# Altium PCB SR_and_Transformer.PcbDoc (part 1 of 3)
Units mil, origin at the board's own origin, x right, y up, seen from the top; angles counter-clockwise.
Board outline 2362.61 x 1852.83 mil, 12 copper layers (Top Layer, Layer 1, Layer 2, Layer 3, Layer 4, Layer 5, Layer 6, Layer 7, Layer 8, Layer 9, Layer 10, Bottom Layer), stack 88.072 mil thick; 104 components, 44 nets, 388 pads, 1030 vias.
Unrouted connection lines stored in the file: 6.
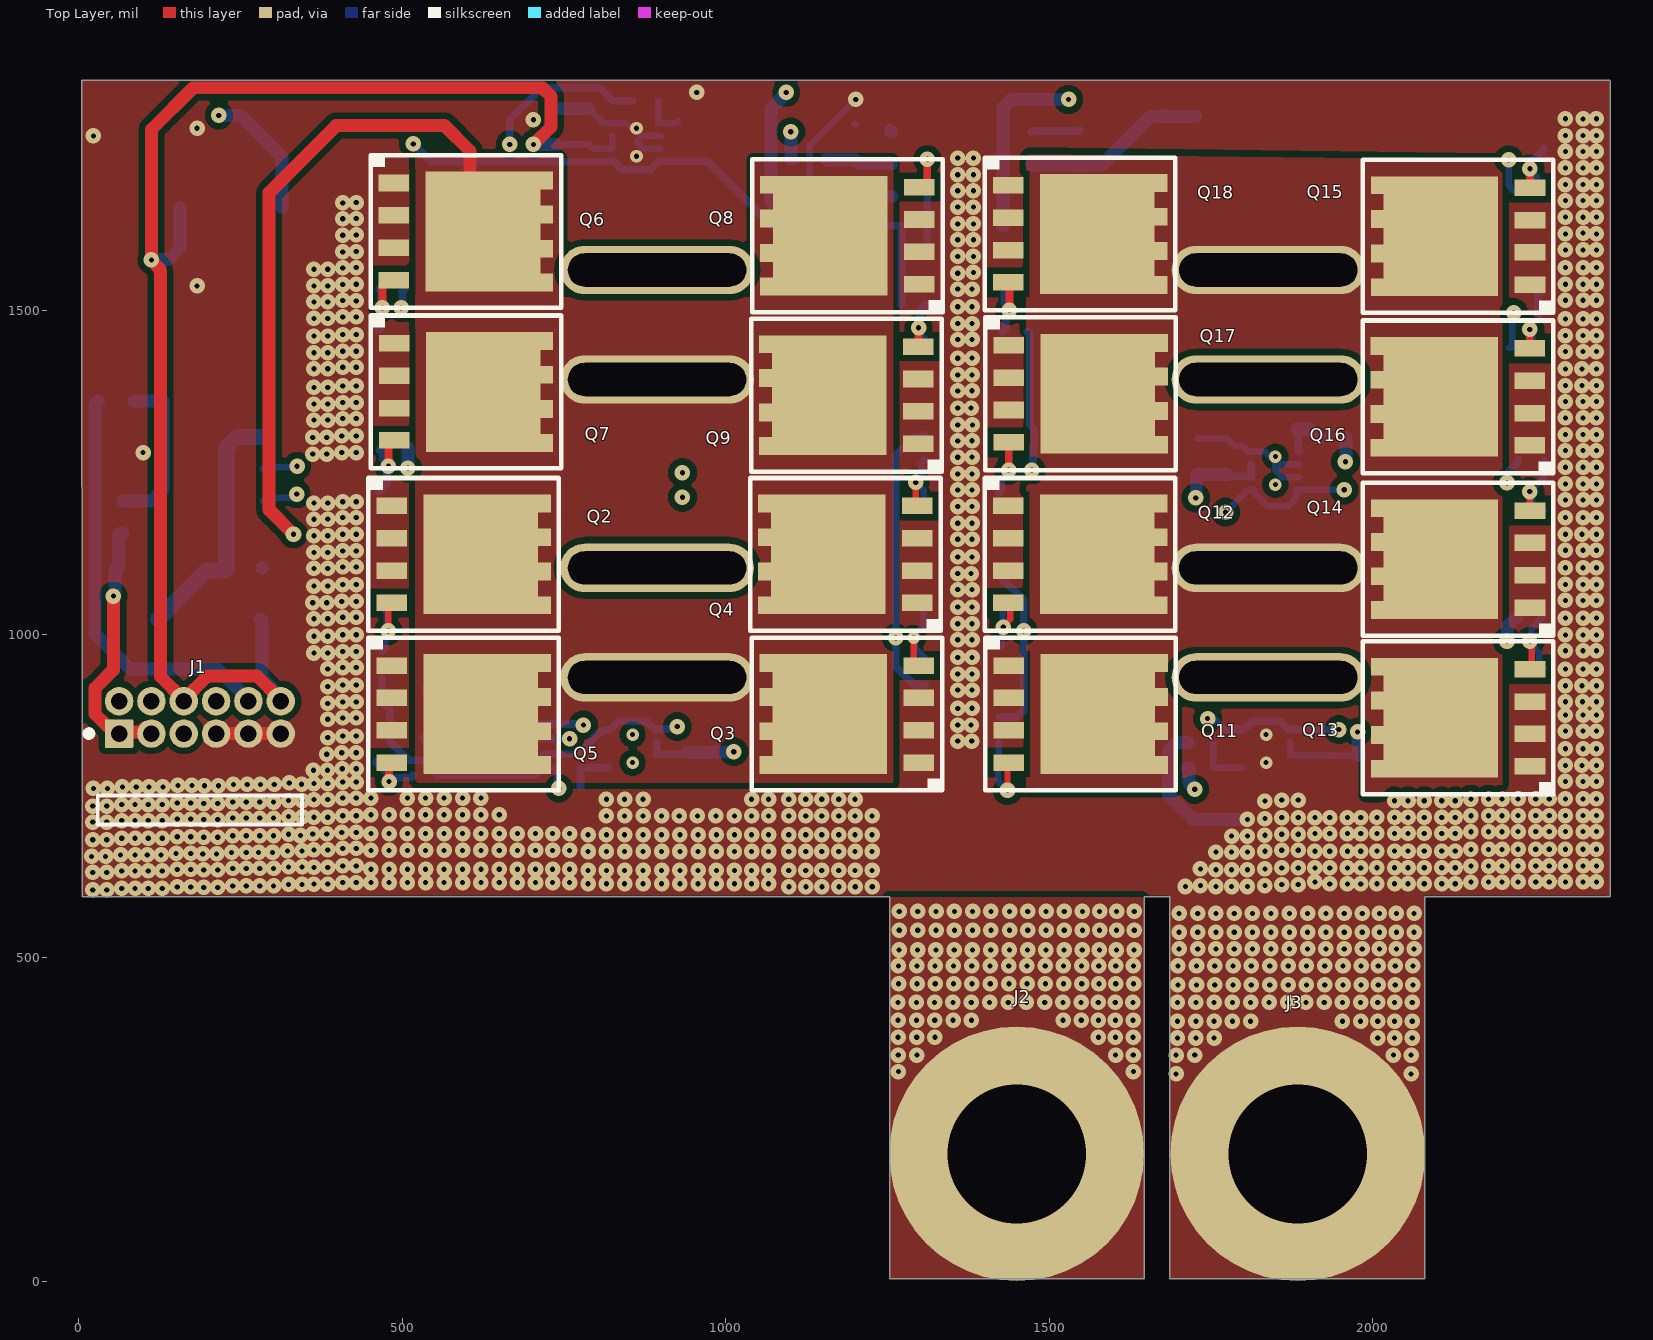
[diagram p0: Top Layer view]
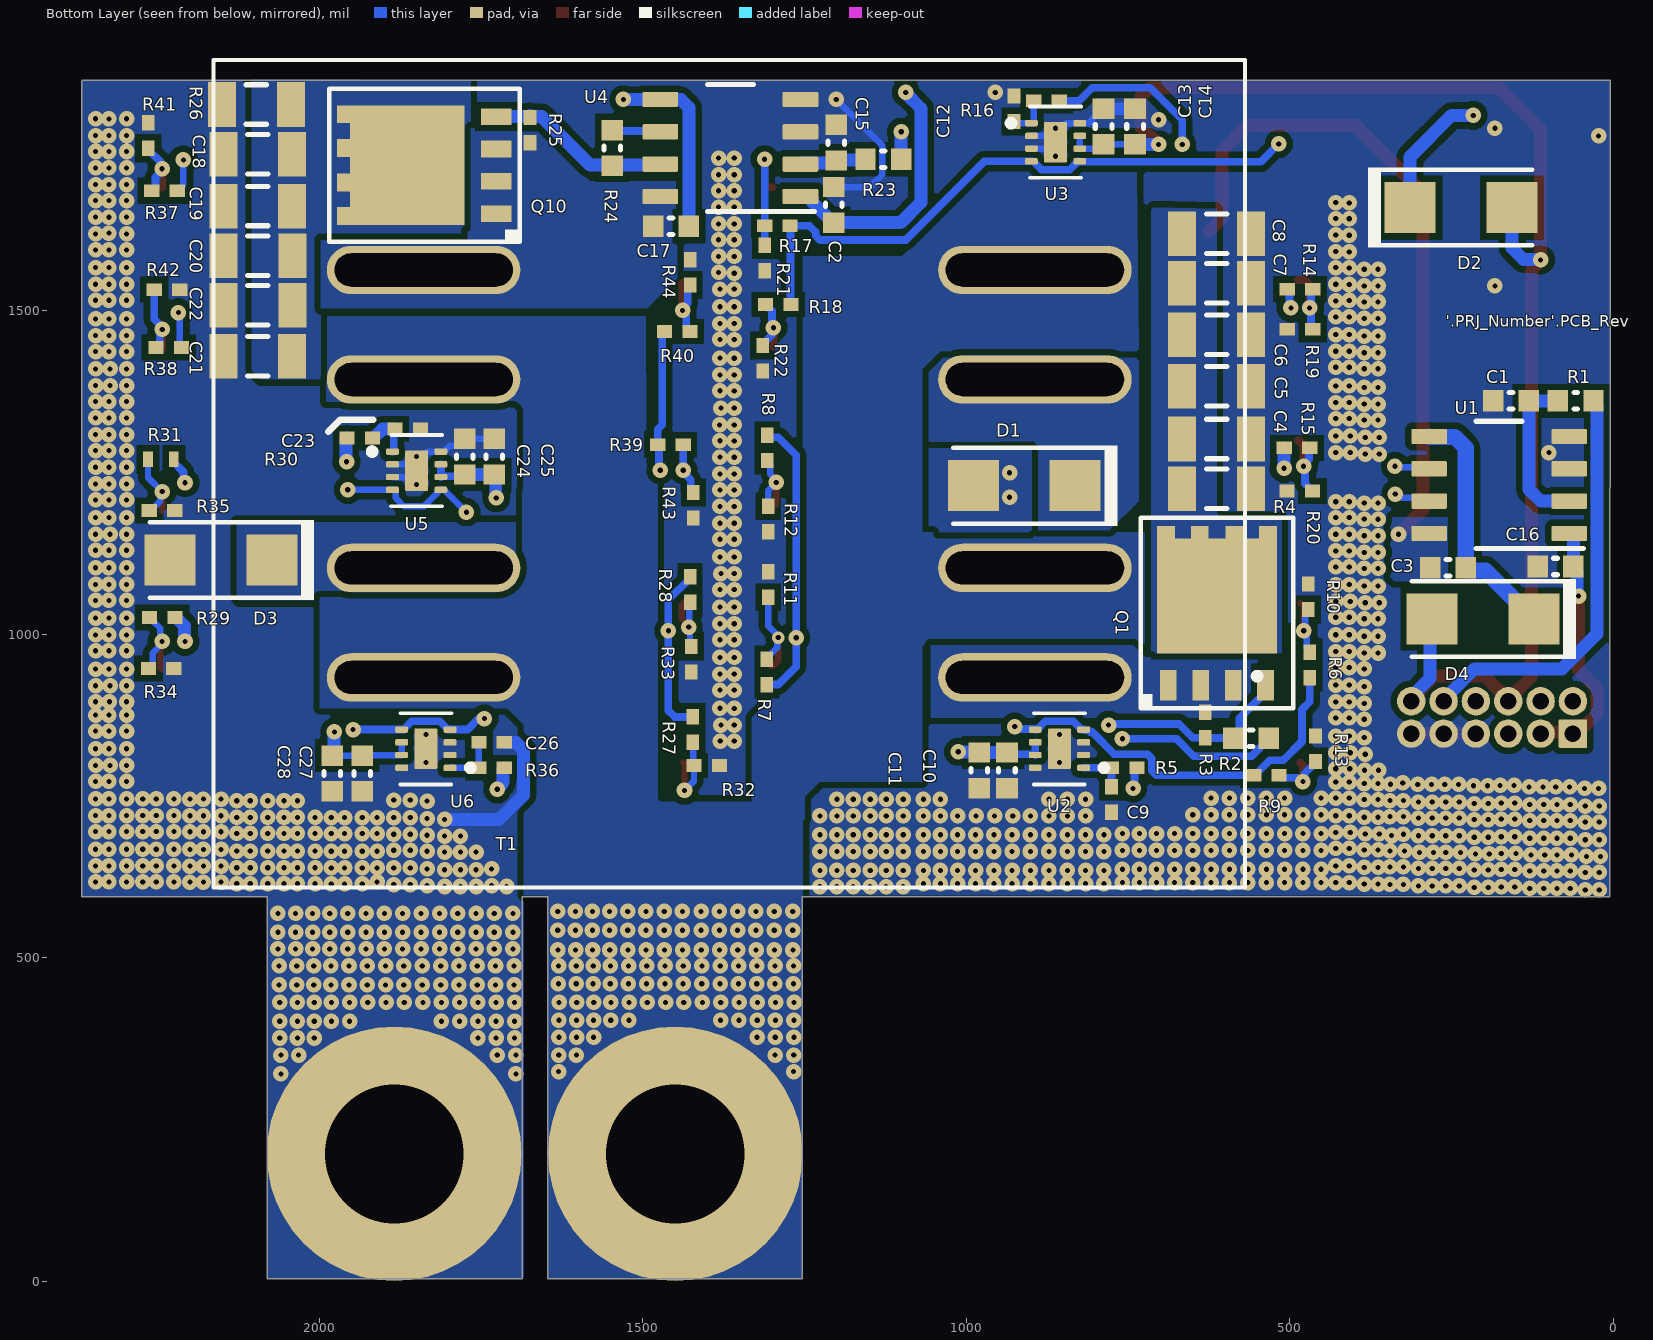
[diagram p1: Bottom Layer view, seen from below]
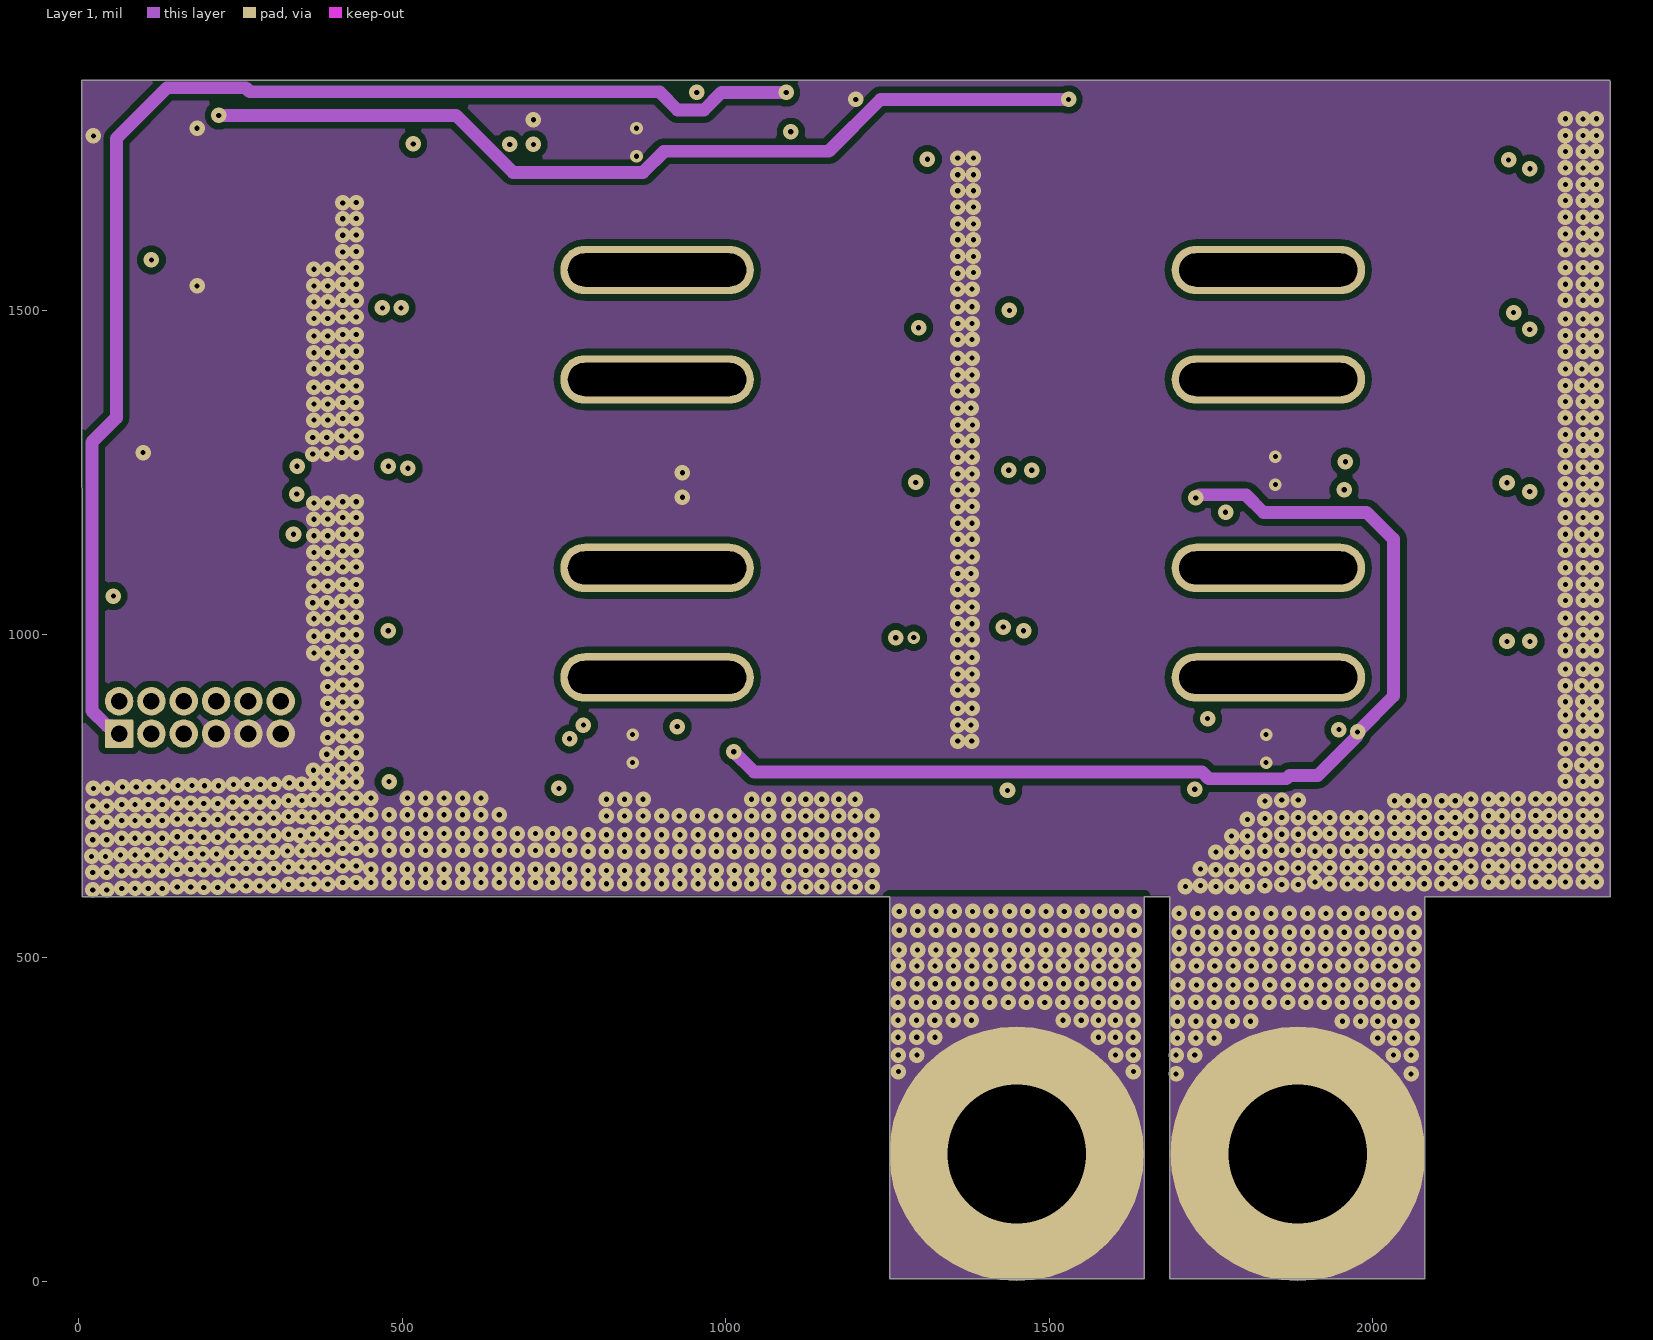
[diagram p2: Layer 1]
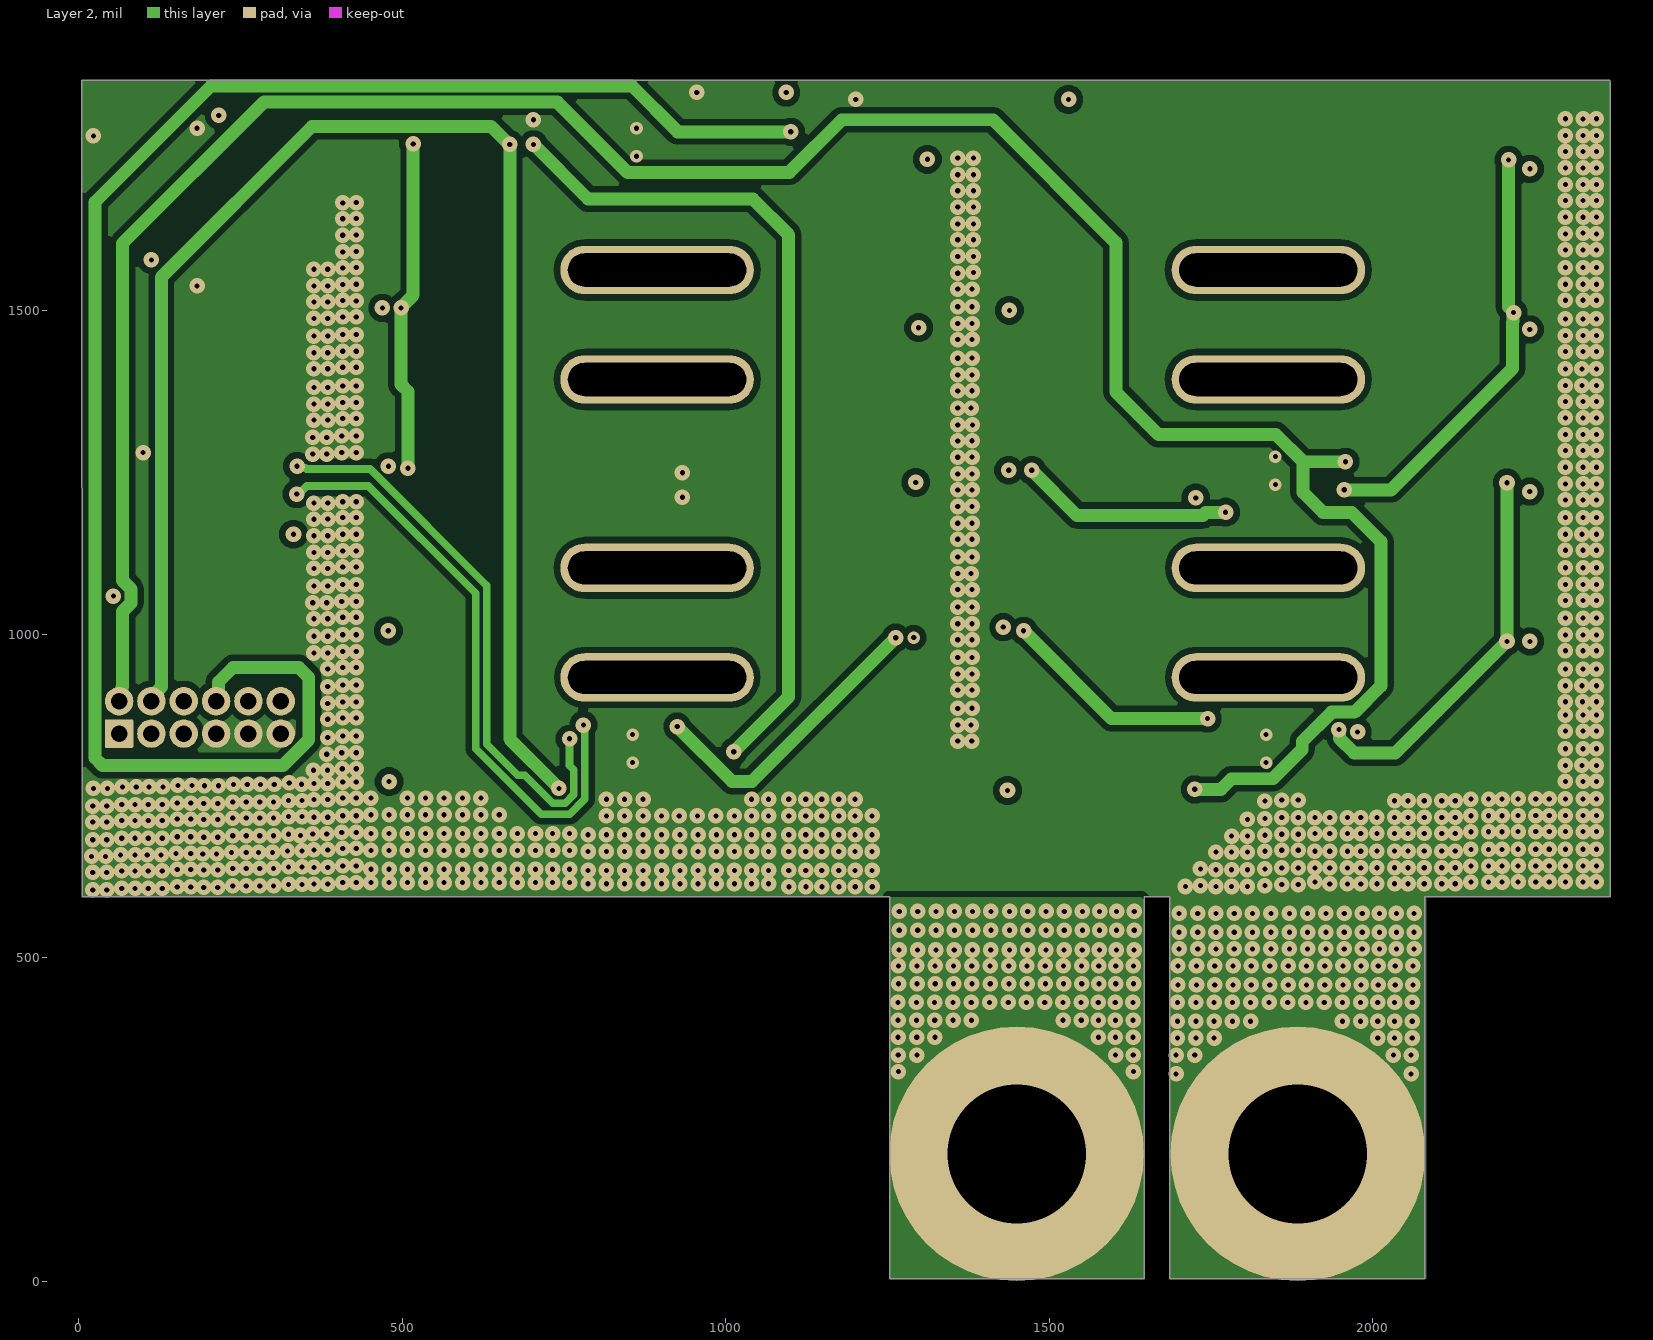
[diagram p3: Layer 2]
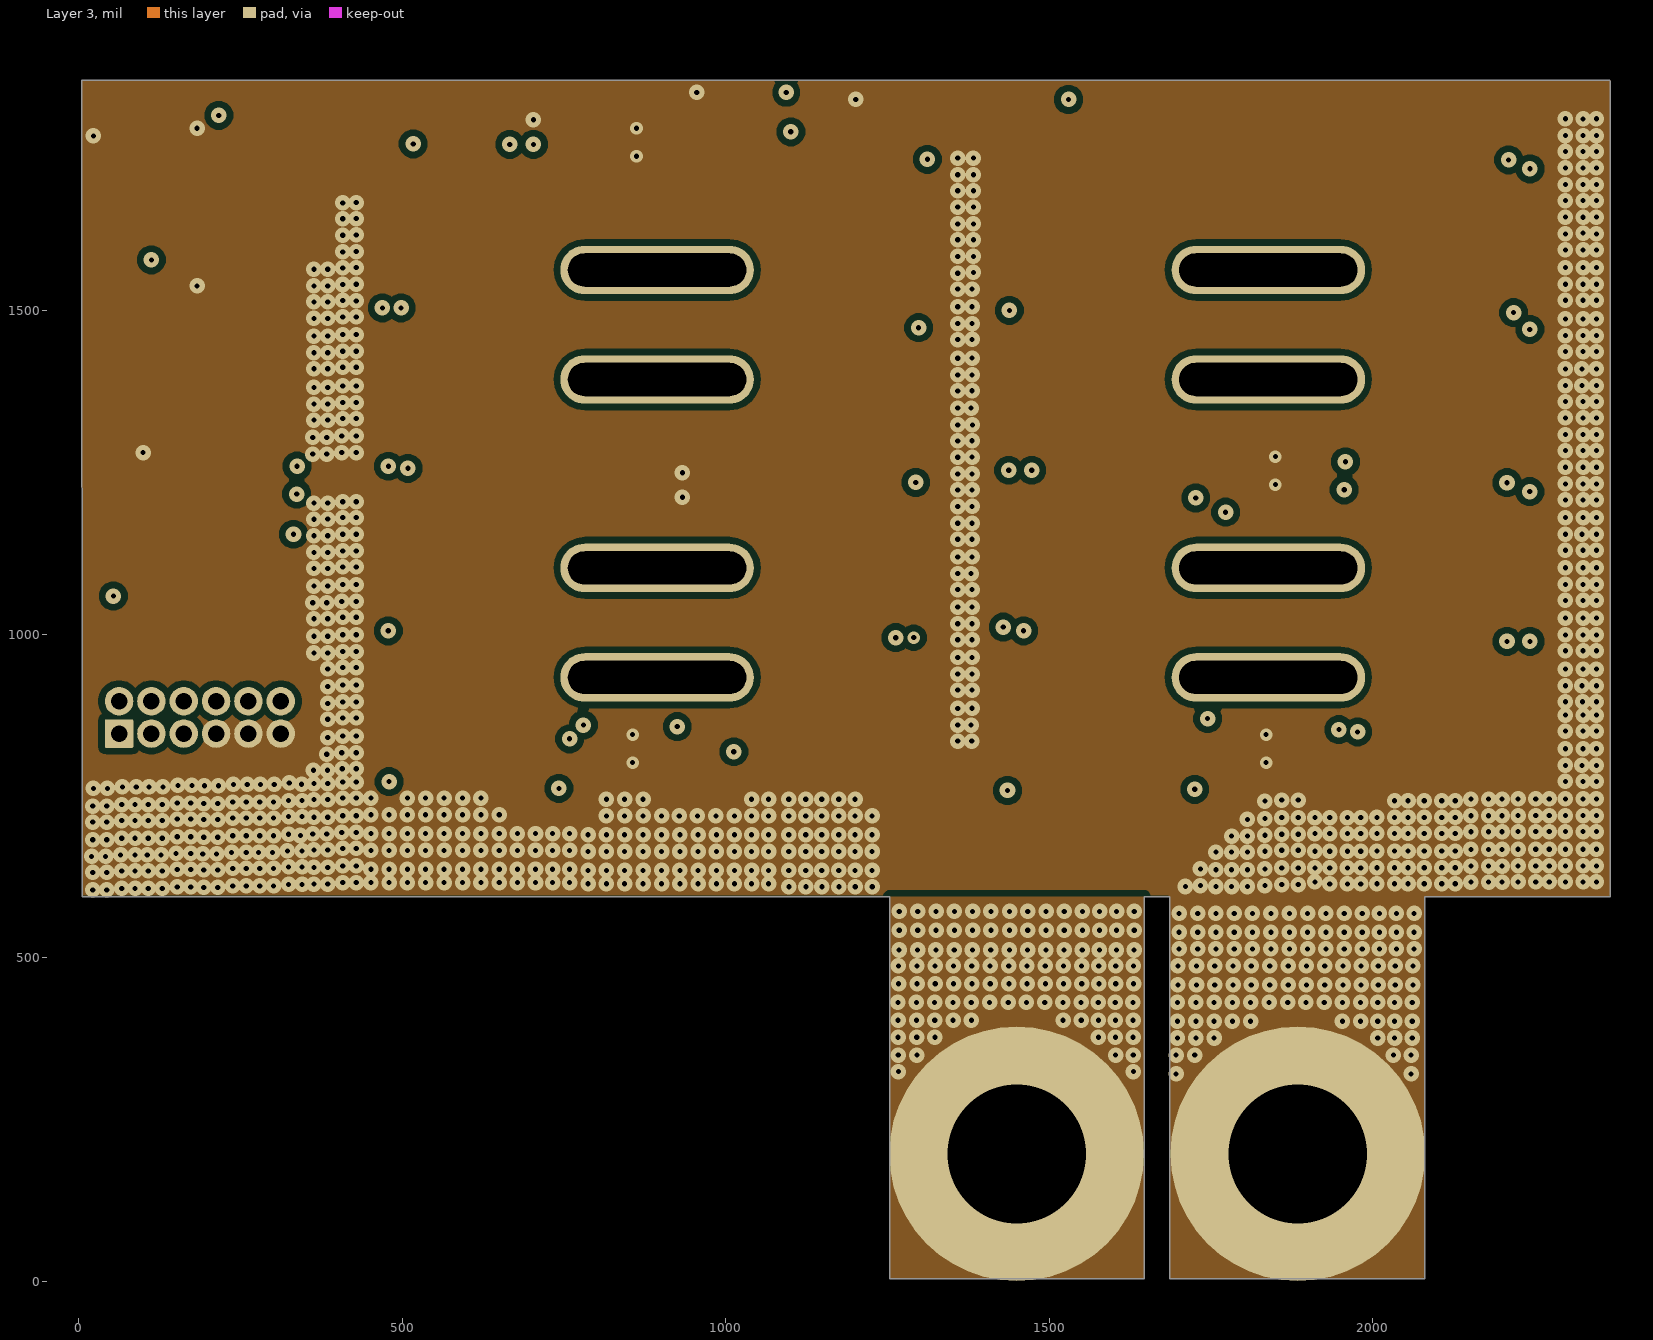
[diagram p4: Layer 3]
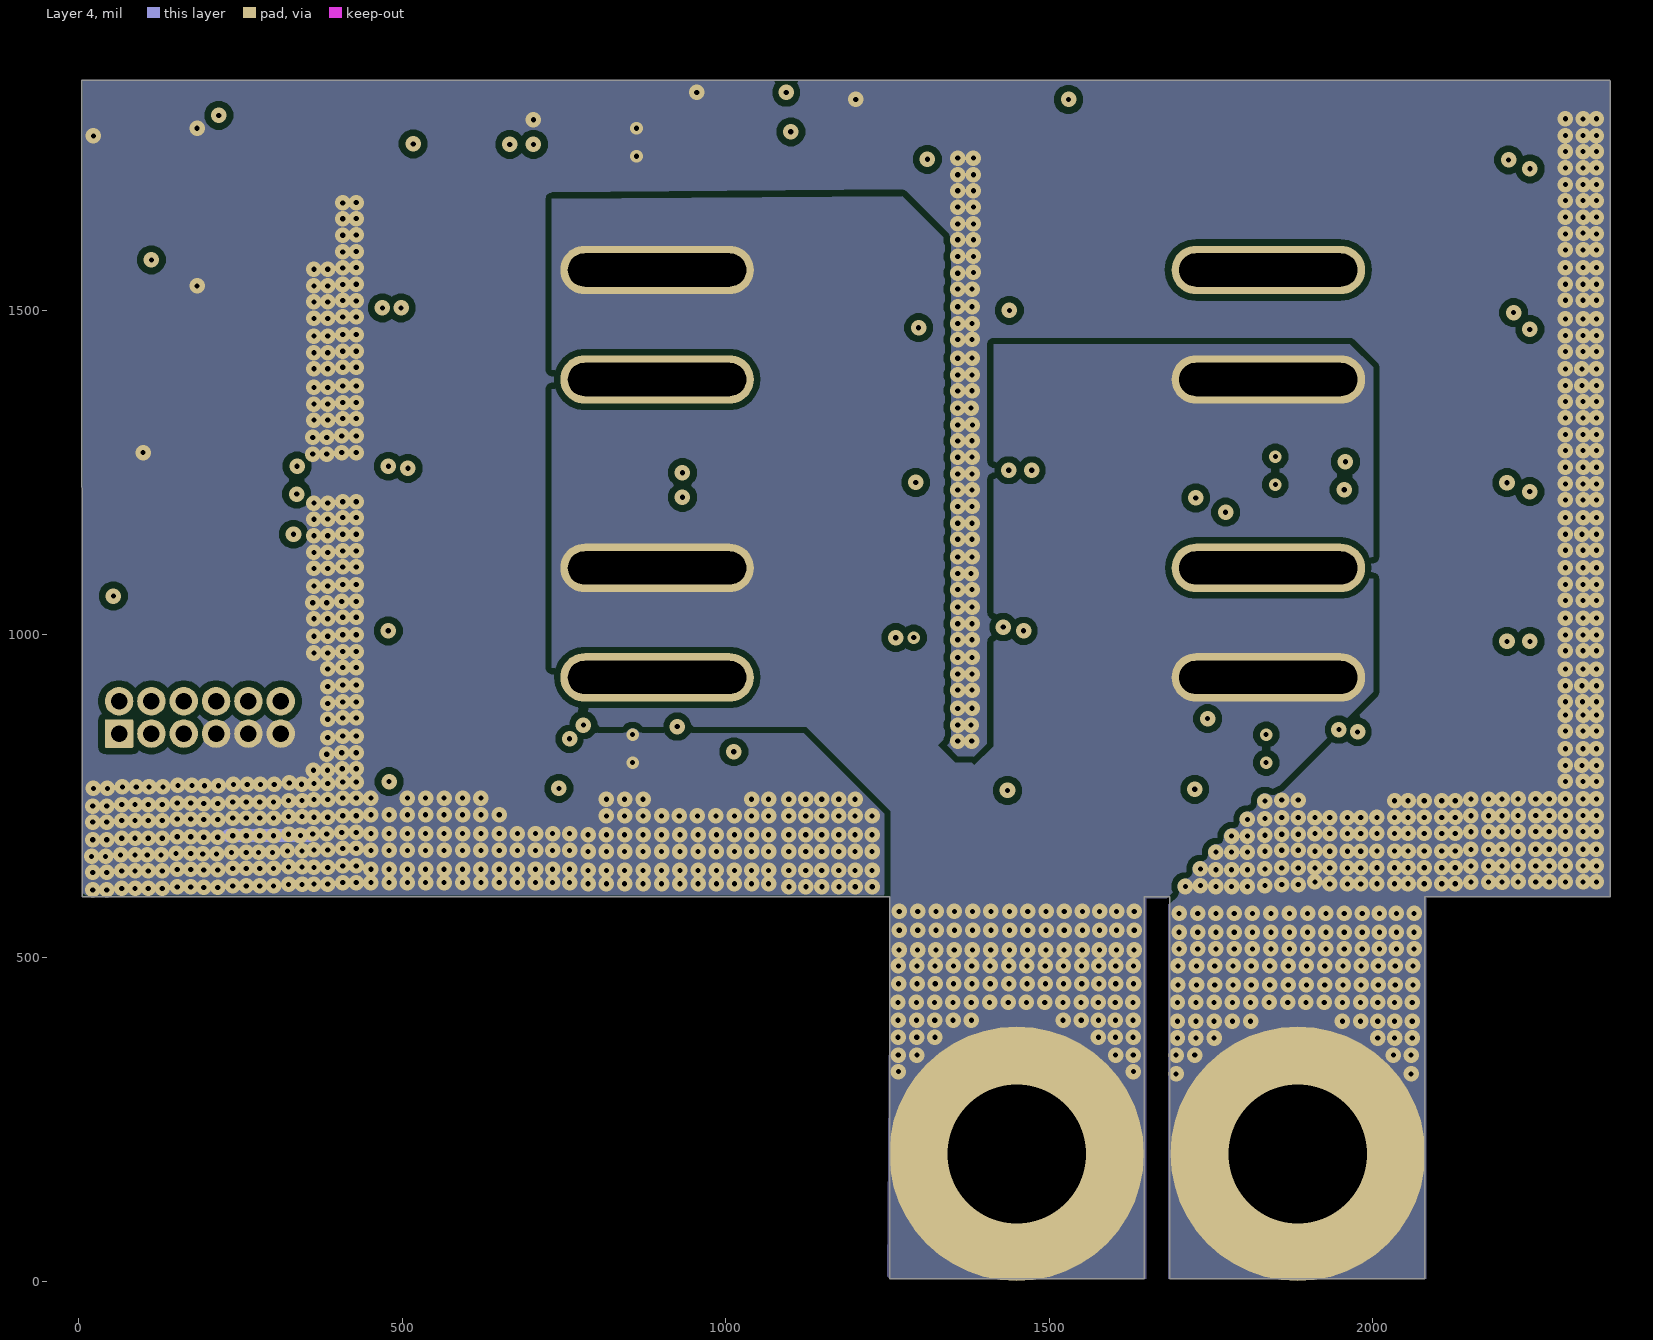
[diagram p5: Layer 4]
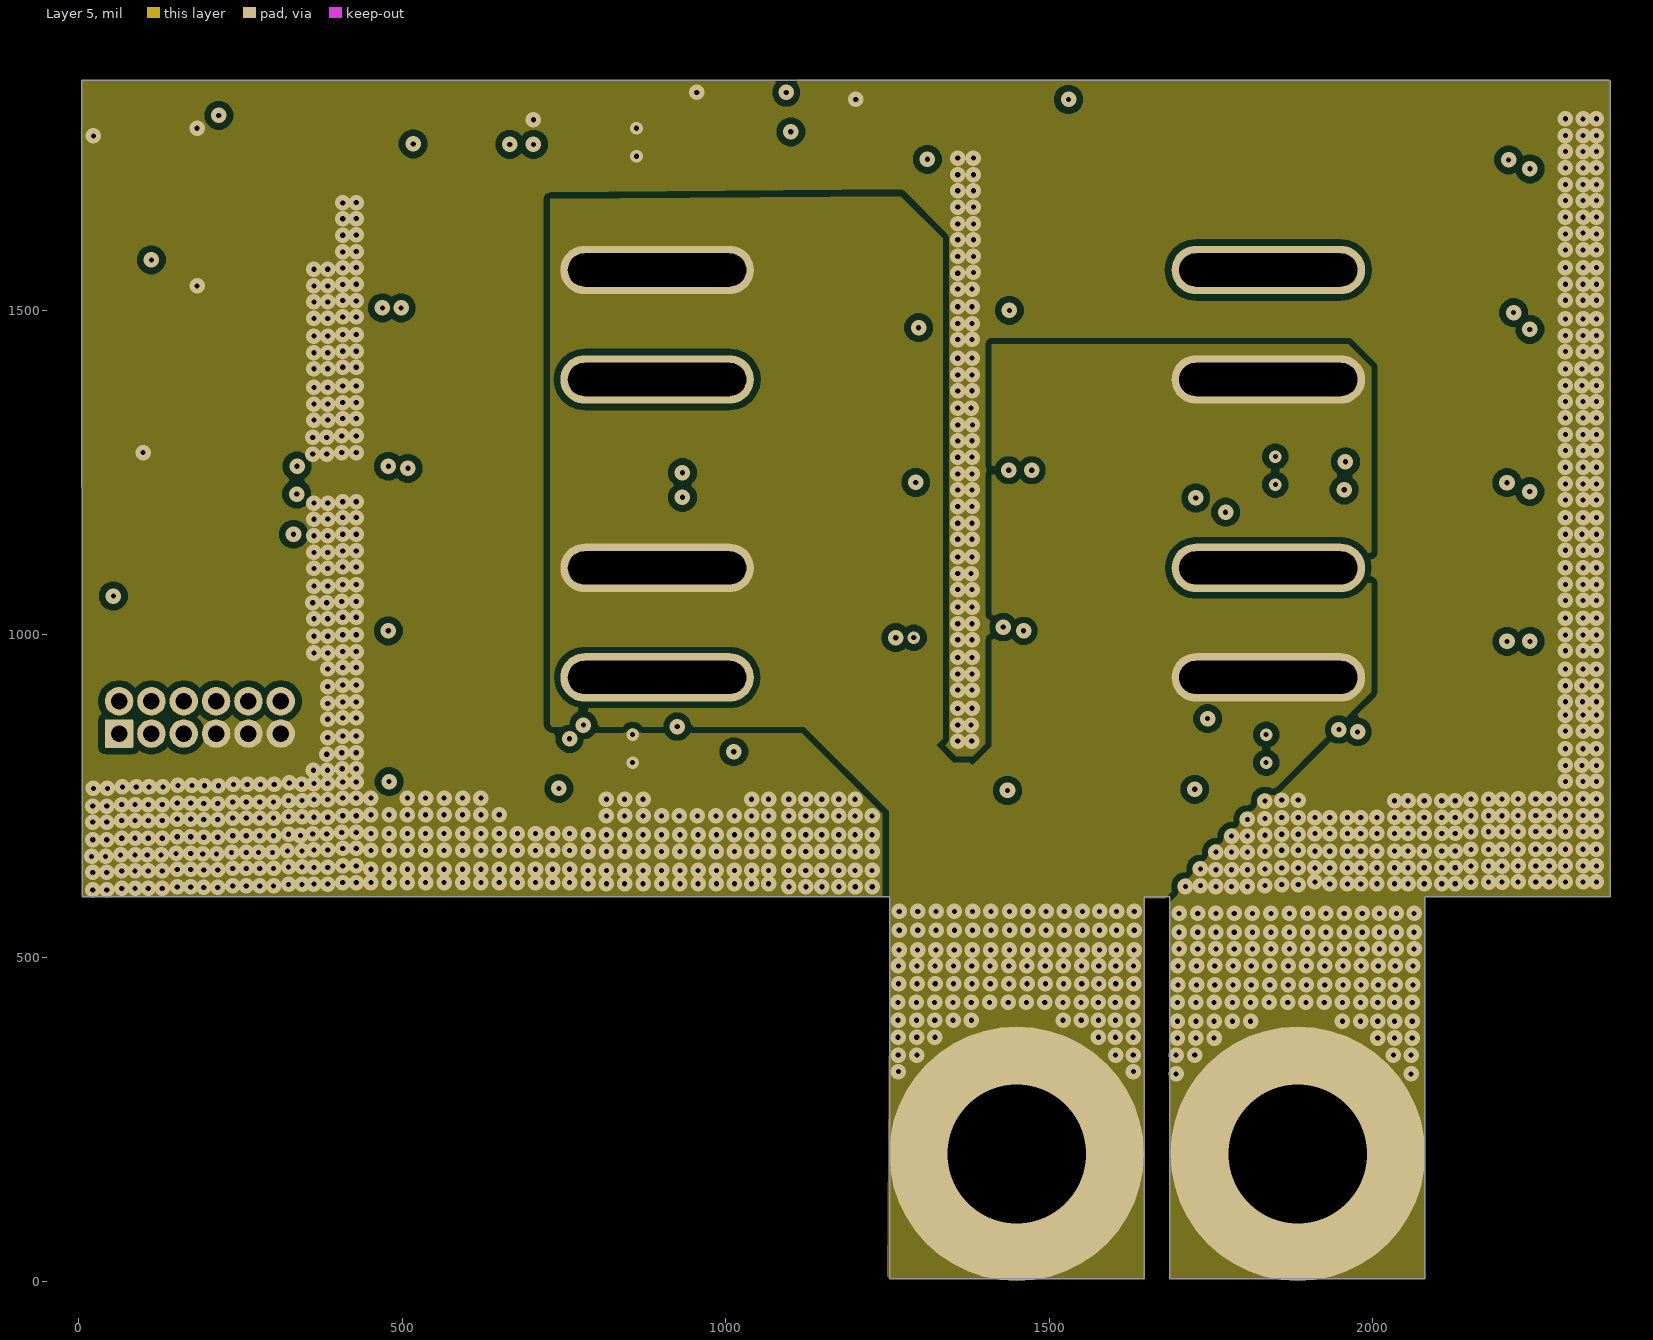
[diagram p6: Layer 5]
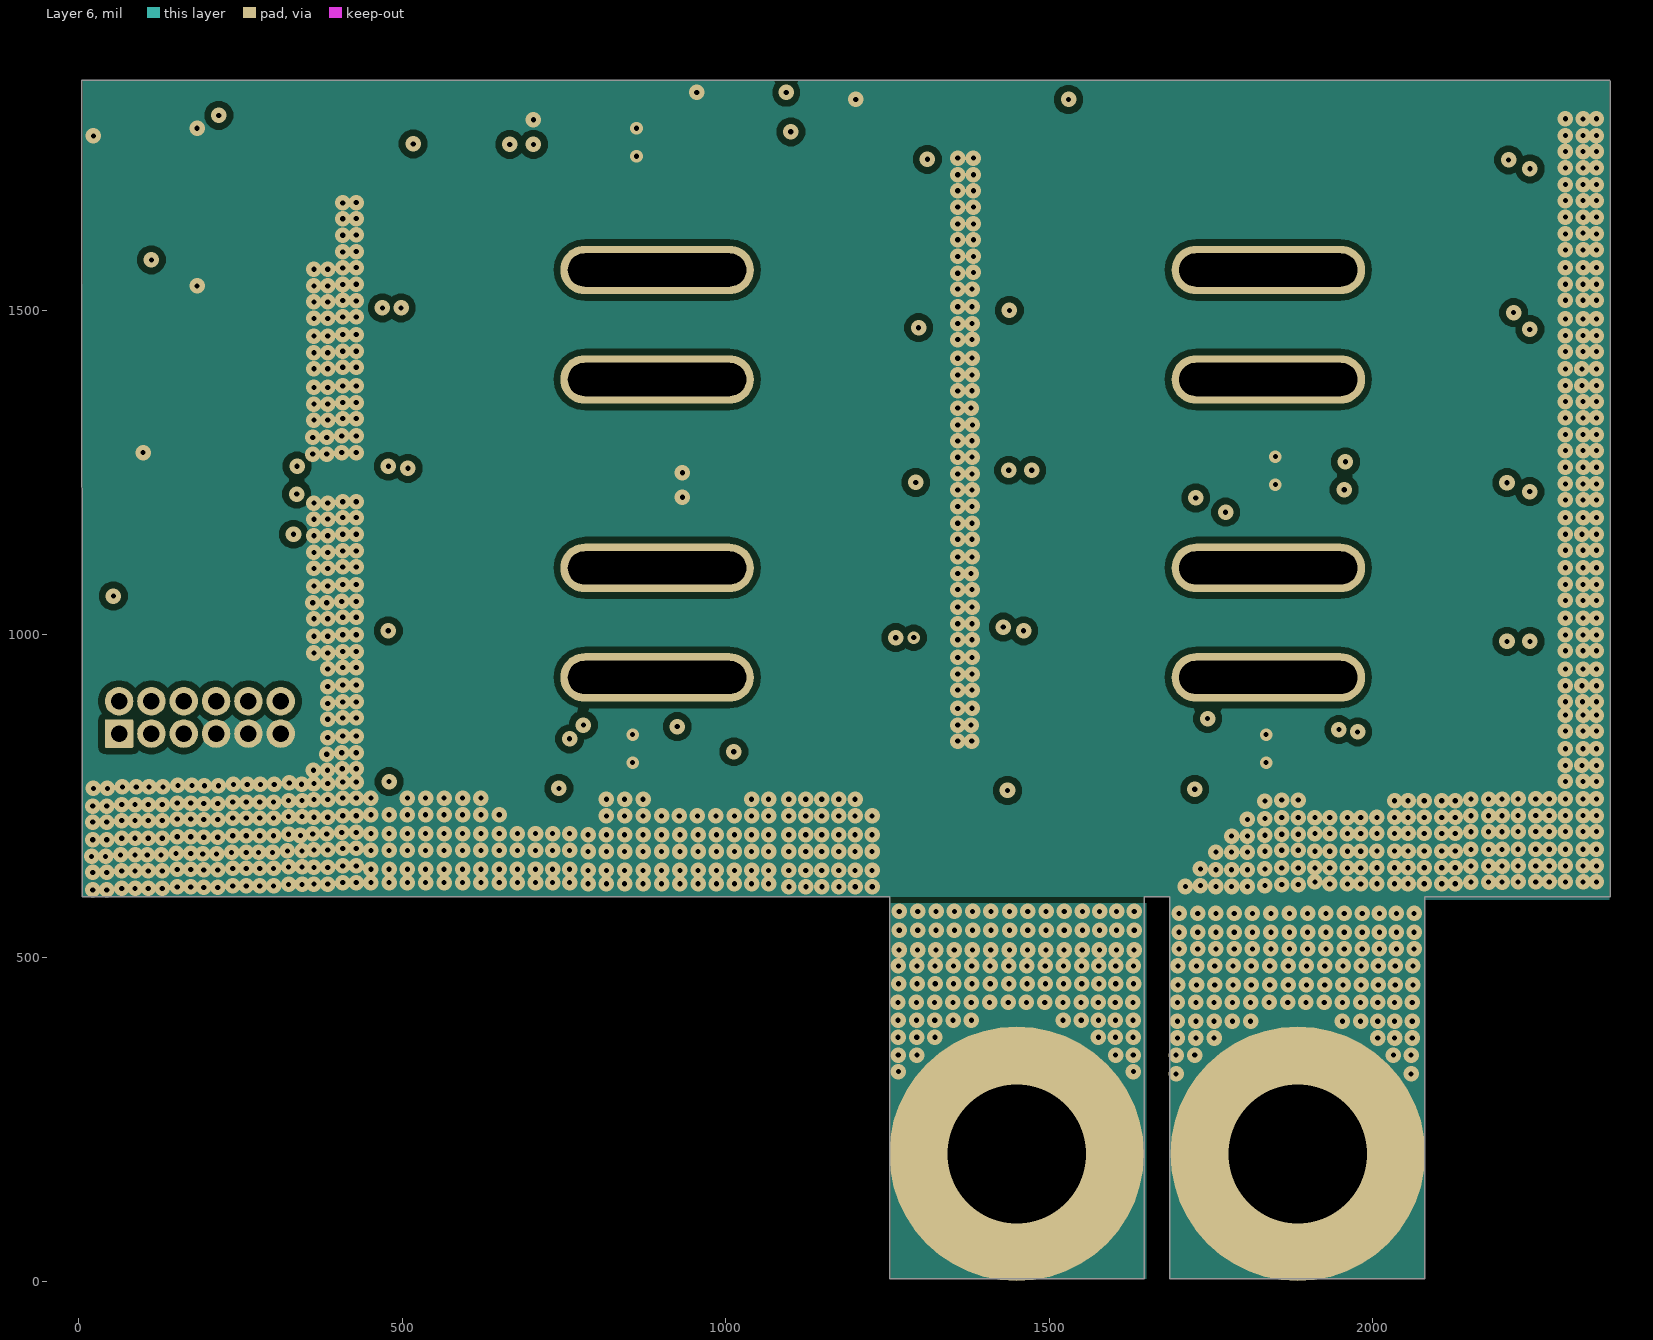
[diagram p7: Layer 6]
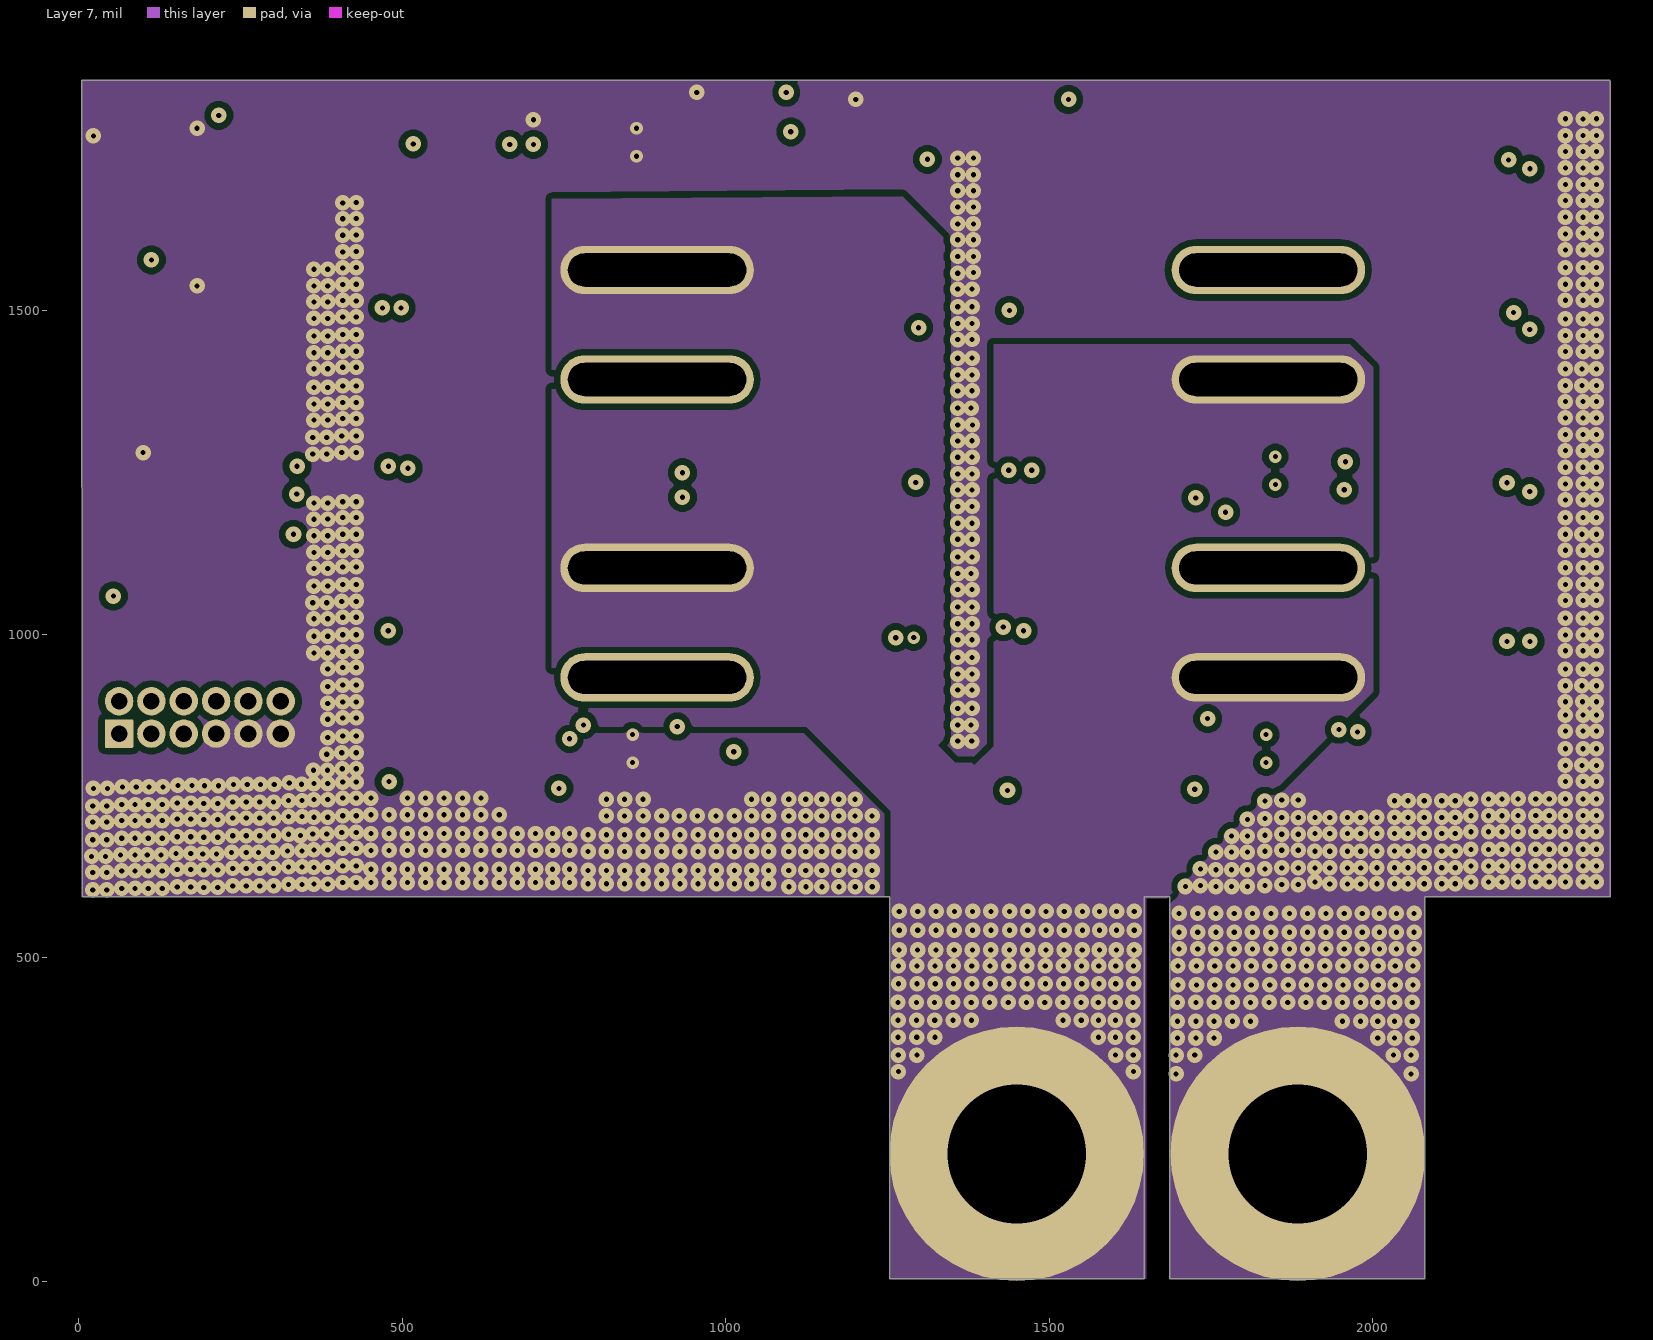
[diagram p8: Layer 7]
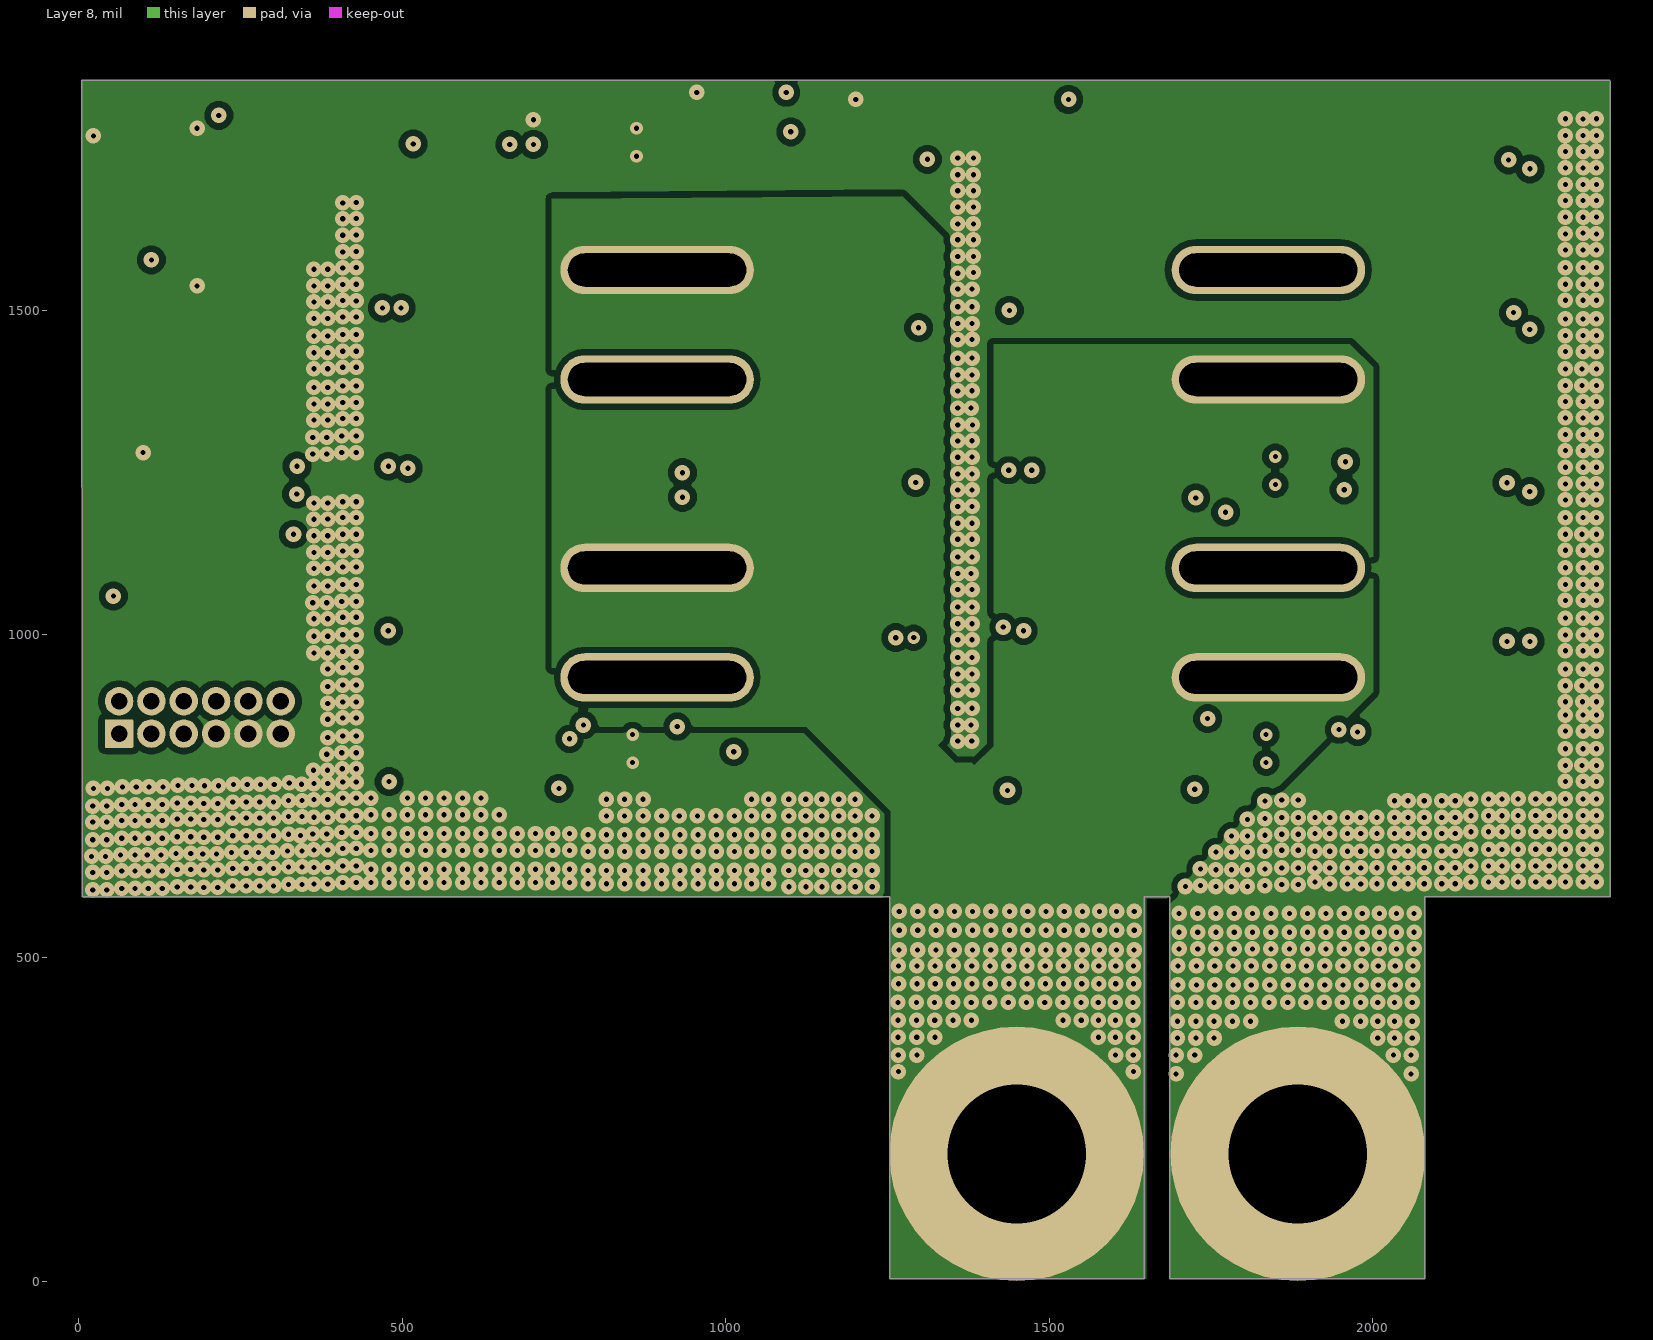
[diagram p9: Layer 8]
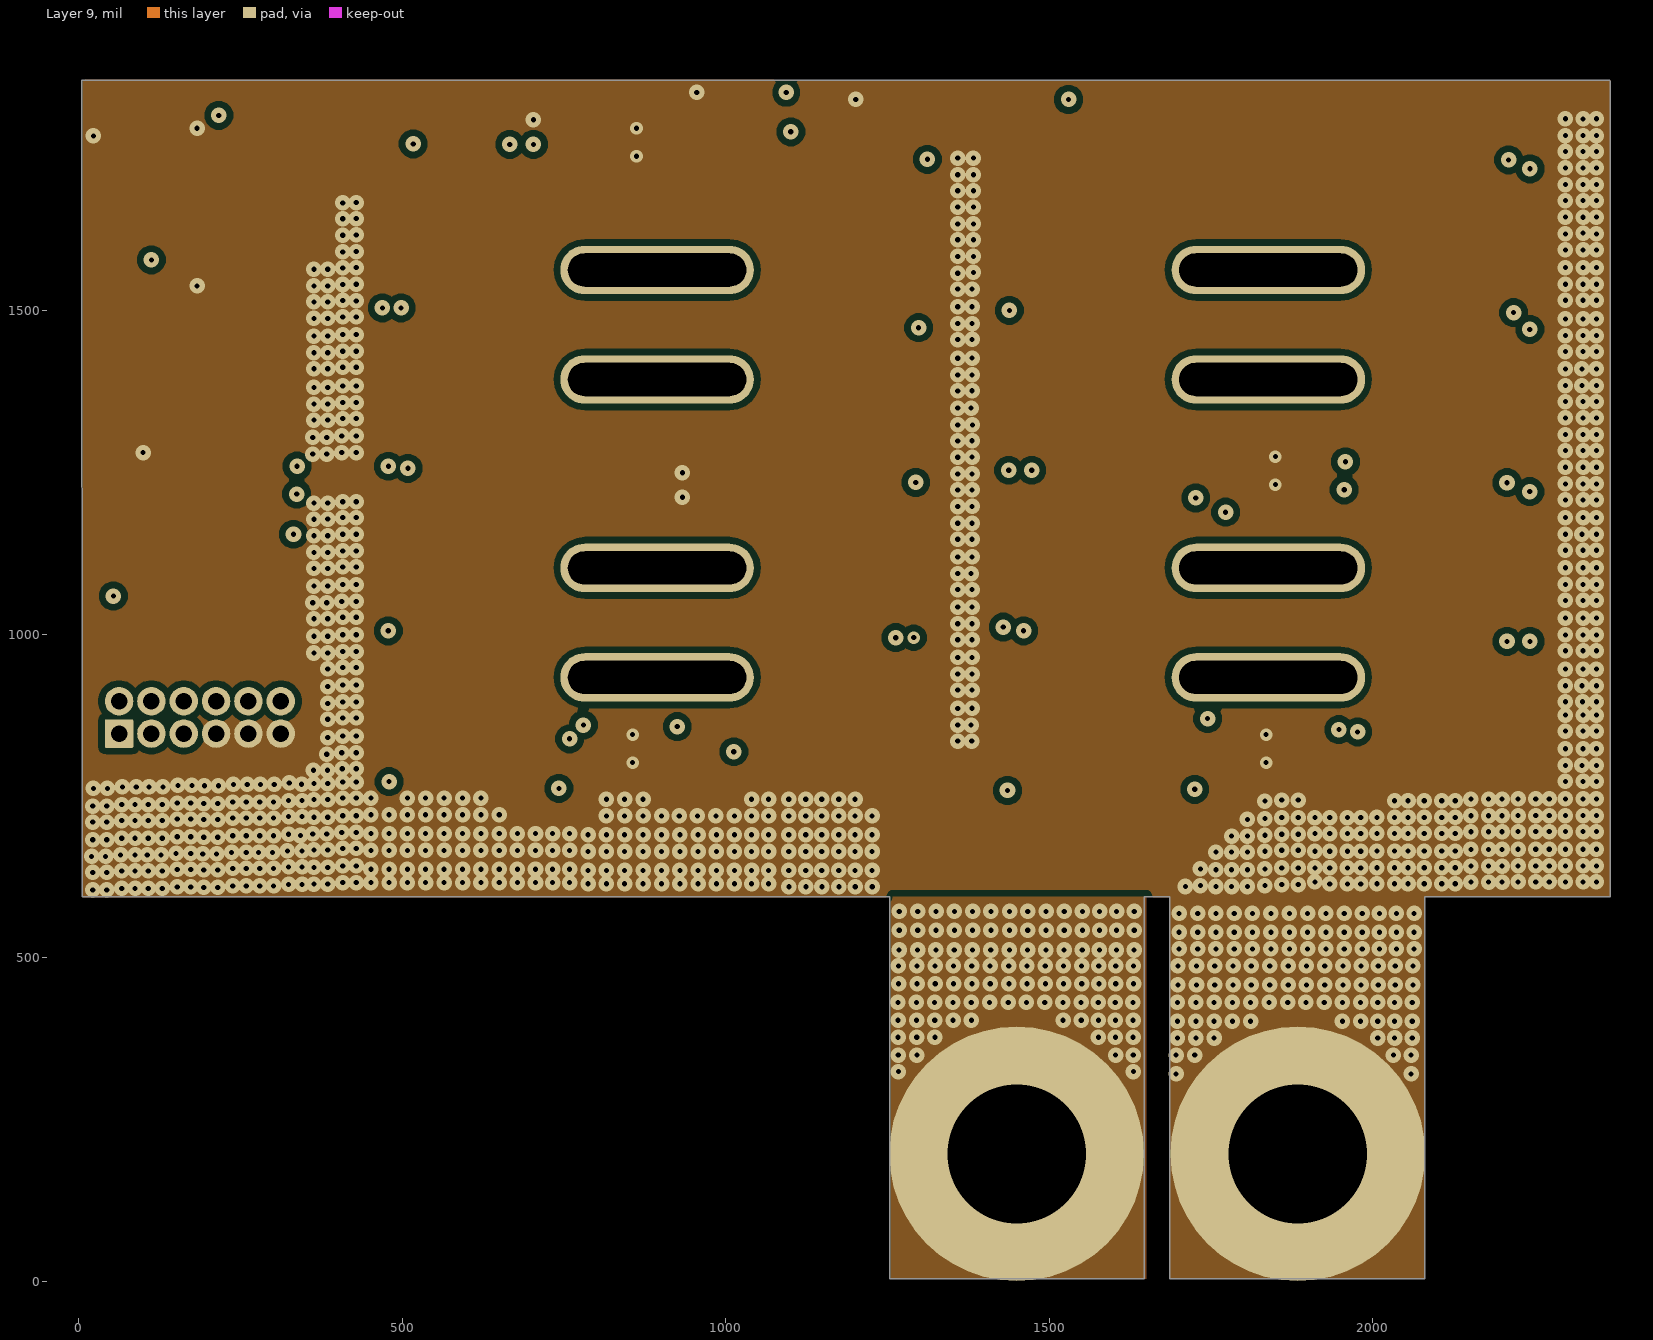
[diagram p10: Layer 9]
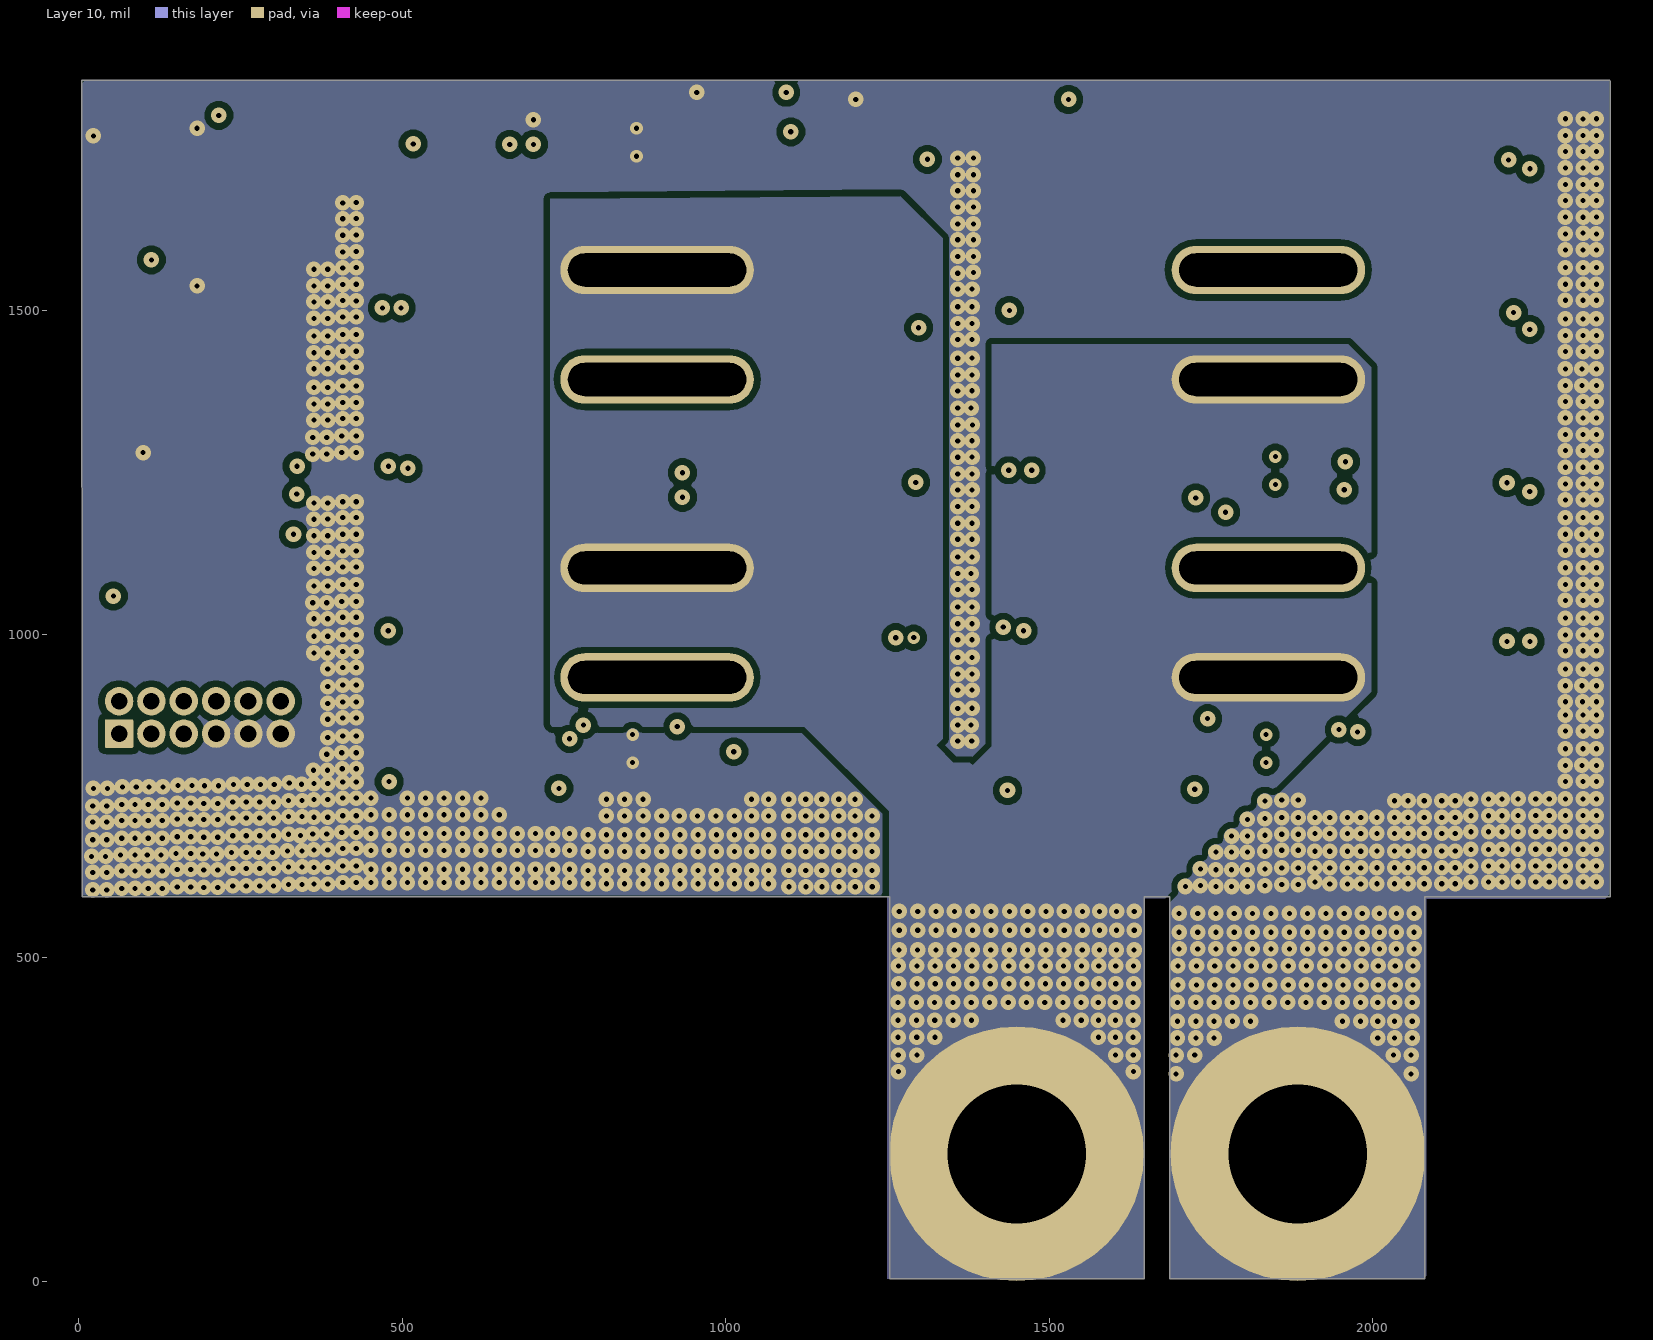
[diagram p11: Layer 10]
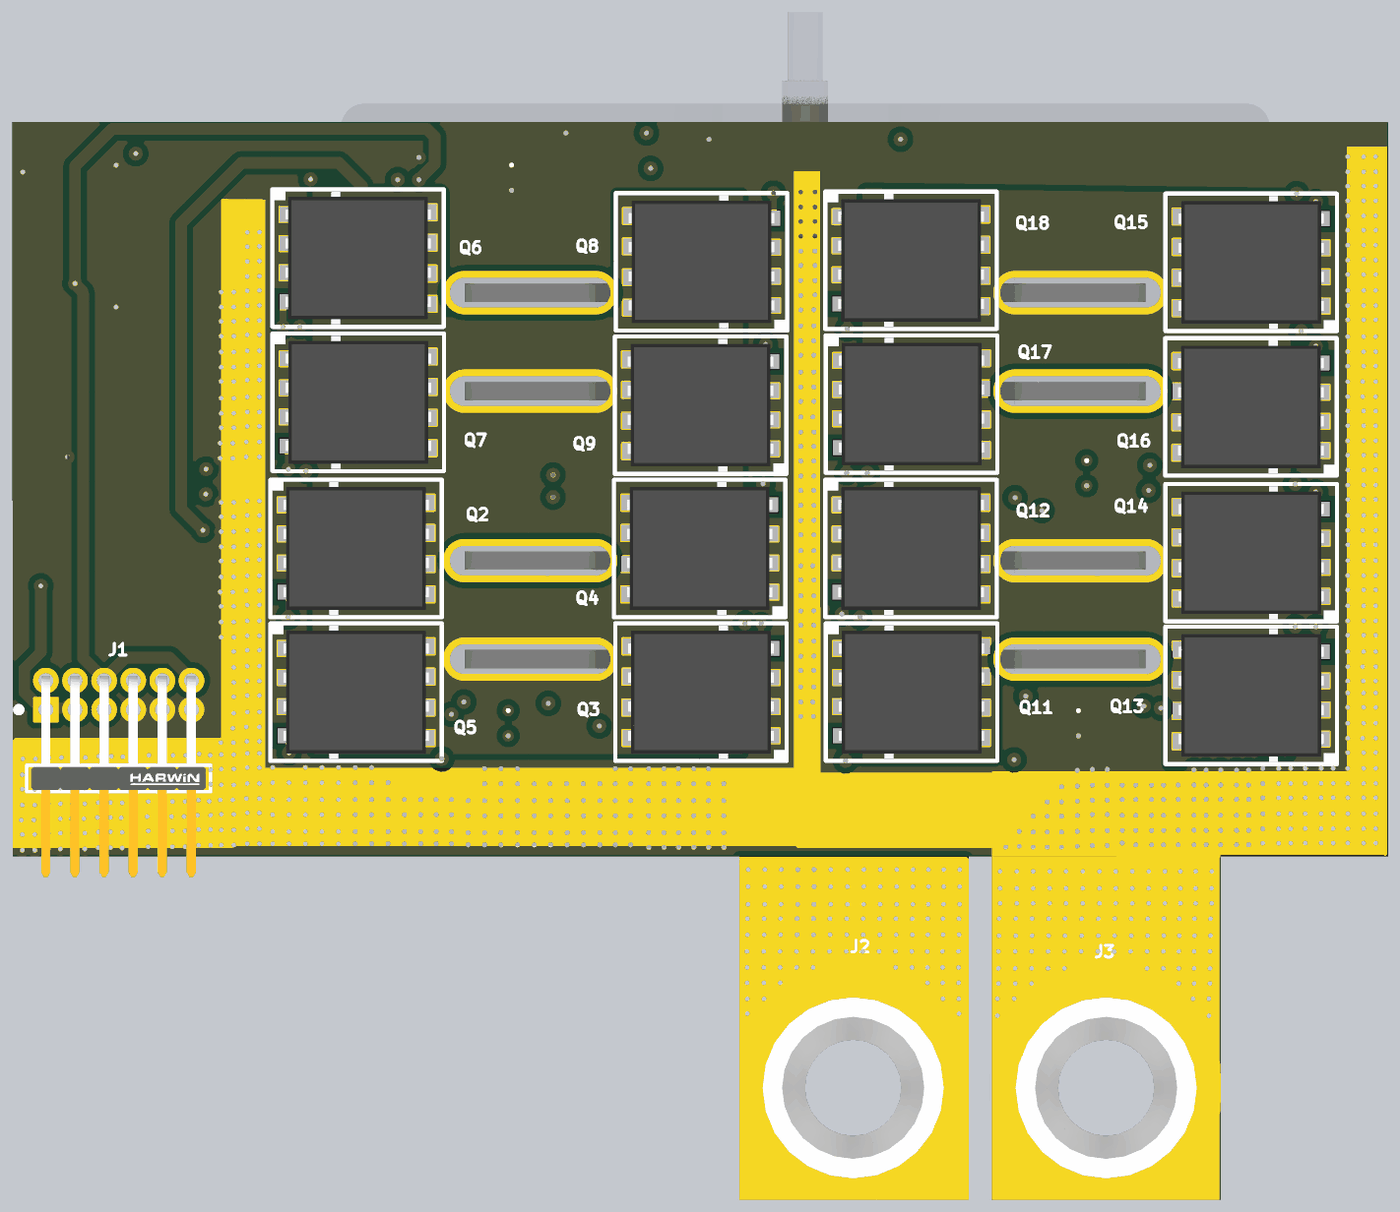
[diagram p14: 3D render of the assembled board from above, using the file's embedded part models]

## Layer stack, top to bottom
Top Solder: solder mask 0.4, Solder Resist, Dk 3.5
Top Layer: signal copper 2.756
Dielectric 1: core 5, FR-4 High Tg, Dk 4.5
Layer 1: signal copper 2.756
Dielectric 2: core 5, FR-4 High Tg, Dk 4.5
Layer 2: signal copper 2.756
Dielectric 3: core 5, FR-4 High Tg, Dk 4.5
Layer 3: signal copper 2.756
Dielectric 4: core 5, FR-4 High Tg, Dk 4.5
Layer 4: signal copper 2.756
Dielectric 5: core 5, Core-009, Dk 4.5
Layer 5: signal copper 2.7559
Dielectric6: core 5, FR-4 High Tg, Dk 4.8
Layer 6: signal copper 2.7559
Dielectric 7: core 5, Core-009, Dk 4.5
Layer 7: signal copper 2.756
Dielectric 8: core 5, FR-4 High Tg, Dk 4.5
Layer 8: signal copper 2.756
Dielectric 9: core 5, FR-4 High Tg, Dk 4.5
Layer 9: signal copper 2.756
Dielectric 10: core 5, FR-4 High Tg, Dk 4.5
Layer 10: signal copper 2.756
Dielectric 11: core 5, FR-4 High Tg, Dk 4.5
Bottom Layer: signal copper 2.756
Bottom Solder: solder mask 0.4, Solder Resist, Dk 3.5

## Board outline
780.97,594.6 820.34,594.6 1214.04,594.6 1253.41,594.6 1253.41,4.05 1647.11,4.05 1647.11,594.6 1686.48,594.6 1686.48,4.05 2080.18,4.05 2080.18,594.6 2367.13,594.6 2366.94,1854.44 2366.72,1856.87 4.52,1856.87 4.92,597.03 4.92,594.6 387.26,594.6

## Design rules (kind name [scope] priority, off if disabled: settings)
AcuteAngle [All] p1: minimum=4.50000000000000E+0001 checktracksonly=FALSE
AssemblyTestPointUsage [All] p1: valid=2
Clearance Clearance_2 [InNetClass('HV') vs Not InNetClass('HV')] p1: gap=60 ignorepadtopadclearanceinfootprint=TRUE except(0: Arc-Hole Track-Hole SMDPad-Hole THPad-Hole Via-Hole Fill-Hole Poly-Hole Region-Hole Text-Hole)
Clearance Clearance_1 [InNetClass('MV') vs Not InNetClass('MV')] p2: gap=40 ignorepadtopadclearanceinfootprint=TRUE
Clearance Clearance_Keepouts [((IsTrack Or IsArc) And Not InPoly) And IsFree and IsKeepOut vs ((IsTrack Or IsArc) And Not InPoly) And IsFree and IsKeepOut] p3: gap=0 ignorepadtopadclearanceinfootprint=FALSE
Clearance Clearance_BoardEdge_MountingHoles [OnCopper and InComponentClass('Mounting Holes') vs IsKeepOut] p4: gap=40 ignorepadtopadclearanceinfootprint=FALSE except(0: Arc-Hole Track-Hole SMDPad-Hole THPad-Hole Via-Hole Fill-Hole Poly-Hole Region-Hole Text-Hole)
Clearance Clearance_BoardEdge_Poly [OnCopper and InPoly vs IsKeepOut] p5: gap=25 ignorepadtopadclearanceinfootprint=FALSE except(0: Arc-Hole Track-Hole SMDPad-Hole THPad-Hole Via-Hole Fill-Hole Poly-Hole Region-Hole Text-Hole)
Clearance Clearance_BoardEdge [OnCopper and Not InComponentClass('Logo') and not InComponentClass('FiducialMark') and not InRegion(1000,500,4000,800) and Not IsKeepout vs IsKeepOut] p6: gap=75 ignorepadtopadclearanceinfootprint=FALSE except(0: Arc-Hole Track-Hole SMDPad-Hole THPad-Hole Via-Hole Fill-Hole Poly-Hole Region-Hole Text-Hole)
Clearance Clearance_Poly [InPolygon] p7: gap=10 ignorepadtopadclearanceinfootprint=FALSE except(0: Arc-Hole Track-Hole SMDPad-Hole THPad-Hole Via-Hole Fill-Hole Poly-Hole Region-Hole Text-Hole)
Clearance [All] p8: gap=7.87 ignorepadtopadclearanceinfootprint=FALSE except(0: Arc-SMDPad Arc-Hole Track-Hole SMDPad-Hole THPad-Hole Via-Hole Fill-Hole Poly-Hole Region-Hole Text-Hole; 5: Arc-Arc Arc-Track Arc-THPad Arc-Via Arc-Fill Track-Track Track-SMDPad Track-THPad Track-Via Track-Fill SMDPad-SMDPad SMDPad-THPad SMDPad-Via SMDPad-Fill THPad-THPad THPad-Via THPad-Fill Via-Via Via-Fill Fill-Fill)
ComponentClearance ComponentClearance_MountingHoles_FiducialMarks [InComponentClass('Mounting Holes') vs InComponentClass('FiducialMark')] p1: gap=20 collisioncheckmode=3 verticalgap=7 showdistances=FALSE
ComponentClearance ComponentClearance_Shunt [InComponentClass('Header') vs InComponentClass('Shunt')] p2: gap=0 collisioncheckmode=3 verticalgap=0 showdistances=FALSE
ComponentClearance ComponentClearance_Logo [InComponentClass('Logo')] p3: gap=5 collisioncheckmode=3 verticalgap=10 showdistances=FALSE
ComponentClearance ComponentClearance_ScrewToNut [(HasFootprint('KEYSTONE_4824')) vs (HasFootprint('Keystone_1903C'))] p4: gap=0 collisioncheckmode=3 verticalgap=0 showdistances=FALSE
ComponentClearance ComponentClearance_MountingHoles [InComponentClass('Mounting Holes')] p5: gap=20 collisioncheckmode=3 verticalgap=7 showdistances=FALSE
ComponentClearance ComponentClearance_SmallPassives [HasFootprint('0201*') or HasFootprint('0402*') or HasFootprint('0508') or HasFootprint('0603*') or HasFootprint('0612') or HasFootprint('0805*') or HasFootprint('0815*') or HasFootprint('0830*') or HasFootprint('1206*') or HasFootprint('1210*') or HasFootprint('1808*') or HasFootprint('1812*') or HasFootprint('1825*') or HasFootprint('2010*') or HasFootprint('2220*') or HasFootprint('2225*') or HasFootprint('2512*') or HasFootprint('2728*') or HasFootprint('3518*') vs HasFootprint('0201*') or HasFootprint('0402*') or HasFootprint('0508') or HasFootprint('0603*') or HasFootprint('0612') or HasFootprint('0805*') or HasFootprint('0815*') or HasFootprint('0830*') or HasFootprint('1206*') or HasFootprint('1210*') or HasFootprint('1808*') or HasFootprint('1812*') or HasFootprint('1825*') or HasFootprint('2010*') or HasFootprint('2220*') or HasFootprint('2225*') or HasFootprint('2512*') or HasFootprint('2728*') or HasFootprint('3518*')] p6: gap=5 collisioncheckmode=3 verticalgap=20 showdistances=FALSE
ComponentClearance ComponentClearance_THtoSMT [IsThruComponent vs IsSMTComponent] p7: gap=10 collisioncheckmode=3 verticalgap=7 showdistances=FALSE
ComponentClearance ComponentClearance_THtoTH [IsThruComponent vs IsThruComponent] p8: gap=10 collisioncheckmode=3 verticalgap=7 showdistances=FALSE
ComponentClearance [All] p9: gap=5 collisioncheckmode=3 verticalgap=7 showdistances=FALSE
DiffPairsRouting [All] p1: maxlimit=100 minlimit=10 mostfreqgap=10 toplayer_minwidth=15 toplayer_maxwidth=15 toplayer_prefwidth=15 midlayer1_minwidth=15 midlayer1_maxwidth=15 midlayer1_prefwidth=15 midlayer2_minwidth=15 midlayer2_maxwidth=15 midlayer2_prefwidth=15 midlayer3_minwidth=15 midlayer3_maxwidth=15 midlayer3_prefwidth=15 midlayer4_minwidth=15 midlayer4_maxwidth=15 midlayer4_prefwidth=15 midlayer5_minwidth=15 midlayer5_maxwidth=15 midlayer5_prefwidth=15 midlayer6_minwidth=15 midlayer6_maxwidth=15 midlayer6_prefwidth=15 midlayer7_minwidth=15 midlayer7_maxwidth=15 midlayer7_prefwidth=15 midlayer8_minwidth=15 midlayer8_maxwidth=15 midlayer8_prefwidth=15 midlayer9_minwidth=15 midlayer9_maxwidth=15 midlayer9_prefwidth=15 midlayer10_minwidth=15 midlayer10_maxwidth=15 midlayer10_prefwidth=15 bottomlayer_minwidth=15 bottomlayer_maxwidth=15 bottomlayer_prefwidth=15 maxuncoupledlength=1000
FabricationTestPointUsage TestPointUsage [All] p1: valid=2 allowmultiple=FALSE
FabricationTestpoint Testpoint [All] p1: side=3 testpointundercomponent=TRUE minsize=40 maxsize=100 preferedsize=60 minholesize=0 maxholesize=40 preferedholesize=32 testpointgrid=1 allowsidetop=TRUE allowsidebottom=TRUE usegrid=TRUE gridtolerance=0.01
FanoutControl Fanout_LCC [IsLCC] p1: bgadir=Out bgaviamode=Centered fanoutstyle=Auto fanoutdirection=Alternating viagrid=1 // Fanout_LCC (Default Rule)
FanoutControl Fanout_BGA [IsBGA] p2: bgadir=Out bgaviamode=Centered fanoutstyle=Auto fanoutdirection=Alternating viagrid=1 // Fanout_BGA (Default Rule)
FanoutControl Fanout_Default [All] p4: bgadir=Out bgaviamode=Centered fanoutstyle=Auto fanoutdirection=Alternating viagrid=1 // Fanout_Default (Default Rule)
FanoutControl Fanout_Small [(CompPinCount < 5)] p5: bgadir=Out bgaviamode=Centered fanoutstyle=Auto fanoutdirection=OutThenIn viagrid=1 // Fanout_Small (Default Rule)
Height [All] p1: minheight=0 maxheight=3000 prefheight=500
HoleSize [All] p1: absolutevalues=TRUE maxlimit=501 minlimit=7 maxpercent=80.000 minpercent=20.000
MinimumAnnularRing MinimumAnnularRing_ThermalPadVias [IsVia and InAnyComponent] p1: minimumring=5.91
MinimumAnnularRing [All] p2: minimumring=5
MinimumSolderMaskSliver MinimumSolderMaskSliver_Logo [InComponentClass('Logo') vs InComponentClass('Logo')] p1: minsoldermaskwidth=0.7
MinimumSolderMaskSliver [All] p2: minsoldermaskwidth=0.7
PlaneConnect [All] p1: planeconnectstyle=Direct reliefexpansion=10 reliefentries=4 reliefconductorwidth=10 reliefairgap=10
PolygonConnect PolygonConnect_16 [All vs IsNamedPolygon('C106_2') Or  IsNamedPolygon('Vout') Or  IsNamedPolygon('IN+') Or  IsNamedPolygon('Q203_5') Or  IsNamedPolygon('IN+') Or  IsNamedPolygon('Q201_5') Or  IsNamedPolygon('C108_2') Or  IsNamedPolygon('SGND') Or  IsNamedPolygon('IN+') Or  IsNamedPolygon('SGND') Or  IsNamedPolygon('Q203_5') Or  IsNamedPolygon('IN+') Or  IsNamedPolygon('SGND') Or  IsNamedPolygon('GND') Or  IsNamedPolygon('C113_2') Or  IsNamedPolygon('C107_2') Or  IsNamedPolygon('C107_2') Or  IsNamedPolygon('Vout') Or  IsNamedPolygon('SIGNAL_LAYER_1_GND_P074') Or  IsNamedPolygon('HV') Or  IsNamedPolygon('C108_2') Or  IsNamedPolygon('C103_2') Or  IsNamedPolygon('Q201_5') Or  IsNamedPolygon('Vout') Or  IsNamedPolygon('C109_2') Or  IsNamedPolygon('Q201_5') Or  IsNamedPolygon('GND') Or  IsNamedPolygon('C107_2') Or  IsNamedPolygon('C102_1') Or  IsNamedPolygon('GND') Or  IsNamedPolygon('SGND') Or  IsNamedPolygon('HS') Or  IsNamedPolygon('Q203_5') Or  IsNamedPolygon('Q201_5') Or  IsNamedPolygon('Q203_5')] p1: connectstyle=Direct reliefconductorwidth=10 reliefentries=4 polygonreliefangle="90 Angle" airgapwidth=10
PolygonConnect PolygonConnect_15 [All vs IsNamedPolygon('C109_2') Or  IsNamedPolygon('C107_2') Or  IsNamedPolygon('HV') Or  IsNamedPolygon('Q203_5') Or  IsNamedPolygon('C107_2') Or  IsNamedPolygon('HS') Or  IsNamedPolygon('Q201_5') Or  IsNamedPolygon('Q203_5') Or  IsNamedPolygon('C106_2') Or  IsNamedPolygon('C108_2') Or  IsNamedPolygon('Vout') Or  IsNamedPolygon('Q203_5') Or  IsNamedPolygon('C108_2') Or  IsNamedPolygon('C113_2') Or  IsNamedPolygon('Q203_5') Or  IsNamedPolygon('Q201_5') Or  IsNamedPolygon('C107_2') Or  IsNamedPolygon('C102_1') Or  IsNamedPolygon('SGND') Or  IsNamedPolygon('GND') Or  IsNamedPolygon('SGND') Or  IsNamedPolygon('GND') Or  IsNamedPolygon('IN+') Or  IsNamedPolygon('IN+') Or  IsNamedPolygon('Q201_5') Or  IsNamedPolygon('Q201_5') Or  IsNamedPolygon('SGND') Or  IsNamedPolygon('SGND') Or  IsNamedPolygon('Vout') Or  IsNamedPolygon('Vout') Or  IsNamedPolygon('IN+') Or  IsNamedPolygon('GND') Or  IsNamedPolygon('IN+') Or  IsNamedPolygon('GND')] p2: connectstyle=Direct reliefconductorwidth=10 reliefentries=4 polygonreliefangle="90 Angle" airgapwidth=10
PolygonConnect PolygonConnect_14 [All vs IsNamedPolygon('C106_2') Or  IsNamedPolygon('C107_2') Or  IsNamedPolygon('C107_2') Or  IsNamedPolygon('C107_2') Or  IsNamedPolygon('C102_1') Or  IsNamedPolygon('Q203_5') Or  IsNamedPolygon('Vout') Or  IsNamedPolygon('Q203_5') Or  IsNamedPolygon('Q203_5') Or  IsNamedPolygon('Q201_5') Or  IsNamedPolygon('C108_2') Or  IsNamedPolygon('Q203_5') Or  IsNamedPolygon('HS') Or  IsNamedPolygon('HV') Or  IsNamedPolygon('C108_2') Or  IsNamedPolygon('Q201_5') Or  IsNamedPolygon('C109_2') Or  IsNamedPolygon('Q201_5') Or  IsNamedPolygon('Q201_5') Or  IsNamedPolygon('C113_2')] p3: connectstyle=Direct reliefconductorwidth=10 reliefentries=4 polygonreliefangle="90 Angle" airgapwidth=10
PolygonConnect PolygonConnect_13 [All vs IsNamedPolygon('C102_1') Or  IsNamedPolygon('HV') Or  IsNamedPolygon('C107_2') Or  IsNamedPolygon('C109_2') Or  IsNamedPolygon('C107_2') Or  IsNamedPolygon('C108_2') Or  IsNamedPolygon('C106_2') Or  IsNamedPolygon('C108_2') Or  IsNamedPolygon('C113_2') Or  IsNamedPolygon('C107_2')] p4: connectstyle=Direct reliefconductorwidth=10 reliefentries=4 polygonreliefangle="90 Angle" airgapwidth=10
PolygonConnect PolygonConnect_12 [All vs IsNamedPolygon('C107_2') Or  IsNamedPolygon('C113_2') Or  IsNamedPolygon('C106_2') Or  IsNamedPolygon('C107_2') Or  IsNamedPolygon('C107_2') Or  IsNamedPolygon('C102_1')] p5: connectstyle=Direct reliefconductorwidth=10 reliefentries=4 polygonreliefangle="90 Angle" airgapwidth=10
PolygonConnect PolygonConnect_11 [All vs IsNamedPolygon('C106_2') Or  IsNamedPolygon('C102_1') Or  IsNamedPolygon('C107_2') Or  IsNamedPolygon('C107_2') Or  IsNamedPolygon('C107_2')] p6: connectstyle=Direct reliefconductorwidth=10 reliefentries=4 polygonreliefangle="90 Angle" airgapwidth=10
PolygonConnect PolygonConnect_10 [All vs IsNamedPolygon('C106_2')] p7: connectstyle=Direct reliefconductorwidth=10 reliefentries=4 polygonreliefangle="90 Angle" airgapwidth=10
PolygonConnect PolygonConnect_9 [All vs IsNamedPolygon('C11_1') Or  IsNamedPolygon('Vin') Or  IsNamedPolygon('Vin') Or  IsNamedPolygon('5V') Or  IsNamedPolygon('D6_2') Or  IsNamedPolygon('Q3_3') Or  IsNamedPolygon('GND2') Or  IsNamedPolygon('GND2') Or  IsNamedPolygon('GND') Or  IsNamedPolygon('Q3_4') Or  IsNamedPolygon('12V5') Or  IsNamedPolygon('GND') Or  IsNamedPolygon('12V5') Or  IsNamedPolygon('D3_1')] p8: connectstyle=Direct reliefconductorwidth=10 reliefentries=4 polygonreliefangle="90 Angle" airgapwidth=10
PolygonConnect PolygonConnect_8 [All vs IsNamedPolygon('C11_1') Or  IsNamedPolygon('Vin') Or  IsNamedPolygon('12V5') Or  IsNamedPolygon('Q3_3') Or  IsNamedPolygon('GND2') Or  IsNamedPolygon('GND2') Or  IsNamedPolygon('5V') Or  IsNamedPolygon('Q3_4') Or  IsNamedPolygon('12V5')] p9: connectstyle=Direct reliefconductorwidth=10 reliefentries=4 polygonreliefangle="90 Angle" airgapwidth=10
PolygonConnect PolygonConnect_7 [All vs IsNamedPolygon('GND2') Or  IsNamedPolygon('GND2') Or  IsNamedPolygon('5V') Or  IsNamedPolygon('12V5') Or  IsNamedPolygon('12V5') Or  IsNamedPolygon('C11_1')] p10: connectstyle=Direct reliefconductorwidth=10 reliefentries=4 polygonreliefangle="90 Angle" airgapwidth=10
PolygonConnect PolygonConnect_6 [All vs IsNamedPolygon('GND2') Or  IsNamedPolygon('SGND') Or  IsNamedPolygon('GND1') Or  IsNamedPolygon('C901_1') Or  IsNamedPolygon('SGND') Or  IsNamedPolygon('GND2') Or  IsNamedPolygon('GND1')] p11: connectstyle=Direct reliefconductorwidth=10 reliefentries=4 polygonreliefangle="90 Angle" airgapwidth=10
PolygonConnect PolygonConnect_5 [All vs IsNamedPolygon('GND1') Or  IsNamedPolygon('GND1')] p12: connectstyle=Direct reliefconductorwidth=10 reliefentries=4 polygonreliefangle="90 Angle" airgapwidth=10
PolygonConnect PolygonConnect_4 [All vs IsNamedPolygon('C21_1') Or  IsNamedPolygon('C5_1') Or  IsNamedPolygon('C12_2') Or  IsNamedPolygon('C2_2') Or  IsNamedPolygon('C13_1') Or  IsNamedPolygon('C28_1') Or  IsNamedPolygon('C6_1') Or  IsNamedPolygon('GND') Or  IsNamedPolygon('GND2') Or  IsNamedPolygon('C14_1') Or  IsNamedPolygon('C13_1') Or  IsNamedPolygon('Q1_3') Or  IsNamedPolygon('C14_1') Or  IsNamedPolygon('C5_1') Or  IsNamedPolygon('GND2') Or  IsNamedPolygon('C28_1') Or  IsNamedPolygon('D5_2') Or  IsNamedPolygon('D6_2') Or  IsNamedPolygon('D2_1') Or  IsNamedPolygon('C12_2') Or  IsNamedPolygon('D2_1') Or  IsNamedPolygon('C4_1') Or  IsNamedPolygon('C4_1') Or  IsNamedPolygon('C2_2') Or  IsNamedPolygon('GND') Or  IsNamedPolygon('C33_1') Or  IsNamedPolygon('C9_1')] p13: connectstyle=Direct reliefconductorwidth=10 reliefentries=4 polygonreliefangle="90 Angle" airgapwidth=10
PolygonConnect PolygonConnect_3 [All vs IsNamedPolygon('C28_1') Or  IsNamedPolygon('C12_2') Or  IsNamedPolygon('C28_1') Or  IsNamedPolygon('C9_1') Or  IsNamedPolygon('D5_2') Or  IsNamedPolygon('C12_2') Or  IsNamedPolygon('C2_2') Or  IsNamedPolygon('C14_1') Or  IsNamedPolygon('C4_1') Or  IsNamedPolygon('C14_1') Or  IsNamedPolygon('D6_2') Or  IsNamedPolygon('GND2') Or  IsNamedPolygon('Q1_3') Or  IsNamedPolygon('C5_1') Or  IsNamedPolygon('D2_1') Or  IsNamedPolygon('C4_1') Or  IsNamedPolygon('C13_1') Or  IsNamedPolygon('C5_1') Or  IsNamedPolygon('C13_1') Or  IsNamedPolygon('C33_1') Or  IsNamedPolygon('D2_1') Or  IsNamedPolygon('GND') Or  IsNamedPolygon('GND') Or  IsNamedPolygon('GND2') Or  IsNamedPolygon('C2_2') Or  IsNamedPolygon('C6_1') Or  IsNamedPolygon('C21_1')] p14: connectstyle=Direct reliefconductorwidth=10 reliefentries=4 polygonreliefangle="90 Angle" airgapwidth=10
PolygonConnect PolygonConnect_2 [All vs IsNamedPolygon('C21_1') Or  IsNamedPolygon('C4_1') Or  IsNamedPolygon('D5_2') Or  IsNamedPolygon('C5_1') Or  IsNamedPolygon('C14_1') Or  IsNamedPolygon('C13_1') Or  IsNamedPolygon('C4_1') Or  IsNamedPolygon('C33_1') Or  IsNamedPolygon('C12_2') Or  IsNamedPolygon('D2_1') Or  IsNamedPolygon('C2_2') Or  IsNamedPolygon('C28_1') Or  IsNamedPolygon('C12_2') Or  IsNamedPolygon('D2_1') Or  IsNamedPolygon('C5_1') Or  IsNamedPolygon('Q1_3') Or  IsNamedPolygon('GND') Or  IsNamedPolygon('D6_2') Or  IsNamedPolygon('C6_1') Or  IsNamedPolygon('C2_2') Or  IsNamedPolygon('C14_1') Or  IsNamedPolygon('C28_1') Or  IsNamedPolygon('C13_1') Or  IsNamedPolygon('C9_1') Or  IsNamedPolygon('GND')] p15: connectstyle=Direct reliefconductorwidth=10 reliefentries=4 polygonreliefangle="90 Angle" airgapwidth=10
PolygonConnect PolygonConnect_1 [All vs IsNamedPolygon('C28_1') Or  IsNamedPolygon('D5_2') Or  IsNamedPolygon('C5_1') Or  IsNamedPolygon('C5_1') Or  IsNamedPolygon('D2_1') Or  IsNamedPolygon('C21_1') Or  IsNamedPolygon('C9_1') Or  IsNamedPolygon('C4_1') Or  IsNamedPolygon('C14_1') Or  IsNamedPolygon('C28_1') Or  IsNamedPolygon('C6_1') Or  IsNamedPolygon('C12_2') Or  IsNamedPolygon('C33_1') Or  IsNamedPolygon('C4_1') Or  IsNamedPolygon('C13_1') Or  IsNamedPolygon('C12_2') Or  IsNamedPolygon('D6_2') Or  IsNamedPolygon('C2_2') Or  IsNamedPolygon('C14_1') Or  IsNamedPolygon('D2_1') Or  IsNamedPolygon('C2_2') Or  IsNamedPolygon('C13_1')] p16: connectstyle=Direct reliefconductorwidth=10 reliefentries=4 polygonreliefangle="90 Angle" airgapwidth=10
PolygonConnect [All] p17: connectstyle=Direct reliefconductorwidth=10 reliefentries=4 polygonreliefangle="90 Angle" airgapwidth=10
RoutingLayers [All] p1: top layer_v5=TRUE mid layer 1_v5=TRUE mid layer 2_v5=TRUE mid layer 3_v5=TRUE mid layer 4_v5=TRUE mid layer 5_v5=FALSE mid layer 6_v5=FALSE mid layer 7_v5=FALSE mid layer 8_v5=FALSE mid layer 9_v5=FALSE mid layer 10_v5=FALSE bottom layer_v5=TRUE
RoutingVias ThermalPadVias [IsVia and not InNet('SGND')and not InNet('Vout')] p1: holewidth=7.87 width=19.68 viastyle="Through Hole" minholewidth=7.87 minwidth=19.68 maxholewidth=17 maxwidth=35
RoutingVias [IsVia and not InNet('SGND')and not InNet('Vout')] p2: holewidth=16 width=34 viastyle="Through Hole" minholewidth=7.87 minwidth=20 maxholewidth=40 maxwidth=65
SilkToBoardRegionClearance [Not ((IsComment or IsDesignator) And (Hide <> 'False')) and not InRegion(1000,500,4000,800)] p1:
SilkToSilkClearance SilkToSilkClearance_Pb-FreeLogo [(HasFootprint('Pb-Free_Overlay_Medium') OR HasFootprint('Pb-Free_Overlay_Small')) vs (HasFootprint('Pb-Free_Overlay_Medium') OR HasFootprint('Pb-Free_Overlay_Small'))] p1: silktosilkclearance=0
SilkToSilkClearance [All] p2: silktosilkclearance=0
SilkToSolderMaskClearance "Silk to Solder Mask Opening" [All] p1: minsilkscreentomaskgap=0 clearancetoexposedcopper=FALSE
SolderMaskExpansion [All] p1: expansion=1.97 istentingtop=FALSE
UnpouredPolygon [All] p1: allowunpoured=TRUE allowshelved=TRUE
Width [All] p1: maxlimit=100 minlimit=6 preferedwidth=10 checkconnectedcopper=TRUE
12 further rules are at their usual default settings.

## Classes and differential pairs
component class SR_Card_B: C15 C16 C17 C18 C19 C20 C21 C22 C23 C24 C25 C26 C27 C28 D2 D3 J2 J3 Q10 Q11 Q12 Q13 Q14 Q15 Q16 Q17 Q18 R23 R24 R25 R26 R27 R28 R29 R30 R31 R32 R33 R34 R35 R36 R37 R38 R39 R40 R41 R42 R43 R44 T1 U4 U5 U6
component class SR_Card_A: C1 C2 C3 C4 C5 C6 C7 C8 C9 C10 C11 C12 C13 C14 D1 D4 J1 Q1 Q2 Q3 Q4 Q5 Q6 Q7 Q8 Q9 R1 R2 R3 R4 R5 R6 R7 R8 R9 R10 R11 R12 R13 R14 R15 R16 R17 R18 R19 R20 R21 R22 U1 U2 U3

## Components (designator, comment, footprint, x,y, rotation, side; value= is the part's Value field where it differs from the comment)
C1 "C0603C470J5GACTU" 0603L 157.81,1361.05 r0 bottom value=47pF
C2 "C0603C105K3RACTU" 0603L 1204.86,1663.94 r90 bottom value=1uF
C3 "C0603C105K3RACTU" 0603L 255.32,1102.69 r0 bottom value=1uF
C4 "GRM31MR71H105KA88L" 1206L 612.9,1301.99 r180 bottom value=1uF
C5 "GRM31MR71H105KA88L" 1206L 612.9,1383.76 r180 bottom value=1uF
C6 "GRM31MR71H105KA88L" 1206L 612.9,1463.14 r180 bottom value=1uF
C7 "GRM31MR71H105KA88L" 1206L 612.9,1542.82 r180 bottom value=1uF
C8 "GRM31MR71H105KA88L" 1206L 612.9,1619.5 r180 bottom value=1uF
C9 "GRM1555C1H470FA01D" 0402L 775.42,744.63 r270 bottom value=47pF
C10 "C0603C104K3RACTU" 0603L 937.03,789.88 r270 bottom value=0.1uF
C11 "CGA3E1X7R1E105K080AC" 0603L 979.93,789.88 r270 bottom value=1uF
C12 "GRM1555C1H470FA01D" 0402L 926.11,1812.56 r90 bottom value=47pF
C13 "C0603C104K3RACTU" 0603L 787.7,1785 r90 bottom value=0.1uF
C14 "CGA3E1X7R1E105K080AC" 0603L 738.94,1785 r90 bottom value=1uF
C15 "C0603C470J5GACTU" 0603L 1200.92,1760 r90 bottom value=47pF
C16 "C0603C105K3RACTU" 0603L 88.94,1104.88 r0 bottom value=1uF
C17 "C0603C105K3RACTU" 0603L 1456.26,1630.95 r0 bottom value=1uF
C18 "GRM31MR71H105KA88L" 1206L 2095.04,1742.03 r0 bottom value=1uF
C19 "GRM31MR71H105KA88L" 1206L 2095.04,1662.12 r0 bottom value=1uF
C20 "GRM31MR71H105KA88L" 1206L 2095,1585 r0 bottom value=1uF
C21 "GRM31MR71H105KA88L" 1206L 2095.04,1430.12 r0 bottom value=1uF
C22 "GRM31MR71H105KA88L" 1206L 2095,1508.98 r0 bottom value=1uF
C23 "GRM1555C1H470FA01D" 0402L 1863.39,1317.77 r180 bottom value=47pF
C24 "C0603C104K3RACTU" 0603L 1775.14,1274.66 r90 bottom value=0.1uF
C25 "CGA3E1X7R1E105K080AC" 0603L 1729.53,1274.66 r90 bottom value=1uF
C26 "GRM1555C1H470FA01D" 0402L 1733.65,833.08 r180 bottom value=47pF
C27 "C0603C104K3RACTU" 0603L 1933.72,785 r270 bottom value=0.1uF
C28 "CGA3E1X7R1E105K080AC" 0603L 1980,785 r270 bottom value=1uF
D1 "3SMAJ5938B-TP" SMA 910.3,1229.81 r0 bottom value=36V
D2 "SS16T3G" SMA 234.96,1659.71 r180 bottom value=60V
D3 "3SMAJ5938B-TP" SMA 2152,1115.06 r0 bottom value=36V
D4 "SS16T3G" SMA 201.21,1023.72 r0 bottom value=60V
J1 "M50-3900642" FP-M50-3900642_HDR12-MFG 187.03,728.45 r0 top
J2 "575-4" Keystone_575-4 1449.73,196.85 r0 top
J3 "575-4" Keystone_575-4 1884.24,196.85 r0 top
Q1 "BSC014N06NSSCATMA1" PG-TDSON-8 612.31,1032.67 r90 bottom value=30V
Q2 "BSC014N06NSSCATMA1" PG-TDSON-8 594.75,1123.62 r0 top value=30V
Q3 "BSC014N06NSSCATMA1" PG-TDSON-8 1187.09,876.74 r180 top value=30V
Q4 "BSC014N06NSSCATMA1" PG-TDSON-8 1184.88,1123.62 r180 top value=30V
Q5 "BSC014N06NSSCATMA1" PG-TDSON-8 594.75,876.74 r0 top value=30V
Q6 "BSC014N06NSSCATMA1" PG-TDSON-8 598.14,1622.73 r0 top value=30V
Q7 "BSC014N06NSSCATMA1" PG-TDSON-8 598.39,1374.8 r0 top value=30V
Q8 "BSC014N06NSSCATMA1" PG-TDSON-8 1188.07,1616.3 r180 top value=30V
Q9 "BSC014N06NSSCATMA1" PG-TDSON-8 1186.49,1369.75 r180 top value=30V
Q10 "BSC014N06NSSCATMA1" PG-TDSON-8 1837.72,1725.32 r0 bottom value=30V
Q11 "BSC014N06NSSCATMA1" PG-TDSON-8 1548.57,876.74 r0 top value=30V
Q12 "BSC014N06NSSCATMA1" PG-TDSON-8 1547.81,1123.62 r0 top value=30V
Q13 "BSC014N06NSSCATMA1" PG-TDSON-8 2131.99,871.04 r180 top value=30V
Q14 "BSC014N06NSSCATMA1" PG-TDSON-8 2131.99,1116.3 r180 top value=30V
Q15 "BSC014N06NSSCATMA1" PG-TDSON-8 2131.99,1615.42 r180 top value=30V
Q16 "BSC014N06NSSCATMA1" PG-TDSON-8 2131.7,1367.08 r180 top value=30V
Q17 "BSC014N06NSSCATMA1" PG-TDSON-8 1548.58,1371.8 r0 top value=30V
Q18 "BSC014N06NSSCATMA1" PG-TDSON-8 1547.81,1618.99 r0 top value=30V
R1 "ERJ-3RQF2R2V" 0603L 57.81,1361.05 r0 bottom value=2.20
R2 "RC0603FR-075R11L" 0603L 559.75,839.45 r180 bottom value=5.11
R3 "RC0402FR-0710KL" 0402L 630.39,859.73 r90 bottom value=10.0k
R4 "RC1206FR-07200KL" 1206L 612.9,1225.22 r0 bottom value=200k
R5 "RCS04022R20FKED" 0402L 755.74,793.71 r0 bottom value=2.20
R6 "RC0402JR-070RL" 0402L 468.77,952.72 r90 bottom value=0
R7 "RC0402JR-070RL" 0402L 1308.15,941.7 r90 bottom value=0
R8 "RC0402JR-070RL" 0402L 1307.55,1288.31 r270 bottom value=0
R9 "RC0402JR-070RL" 0402L 535.95,782.12 r180 bottom value=0
R10 "RT0402BRD0710KL" 0402L 471.23,1058.26 r270 bottom value=10.0k
R11 "RT0402BRD0710KL" 0402L 1305.95,1077.1 r270 bottom value=10.0k
R12 "RT0402BRD0710KL" 0402L 1305.95,1178.17 r90 bottom value=10.0k
R13 "RT0402BRD0710KL" 0402L 460,823.23 r270 bottom value=10.0k
R14 "RC0402JR-070RL" 0402L 483.86,1533.65 r180 bottom value=0
R15 "RC0402JR-070RL" 0402L 488.61,1288.32 r180 bottom value=0
R16 "RCS04022R20FKED" 0402L 875.73,1825 r0 bottom value=2.20
R17 "RC0402JR-070RL" 0402L 1291.91,1631.65 r0 bottom value=0
R18 "RC0402JR-070RL" 0402L 1290.51,1510 r0 bottom value=0
R19 "RT0402BRD0710KL" 0402L 483.86,1471.79 r180 bottom value=10.0k
R20 "RT0402BRD0710KL" 0402L 484.24,1221.55 r180 bottom value=10.0k
R21 "RT0402BRD0710KL" 0402L 1311.59,1581.65 r90 bottom value=10.0k
R22 "RT0402BRD0710KL" 0402L 1314.57,1426.96 r90 bottom value=10.0k
R23 "ERJ-3RQF2R2V" 0603L 1128.09,1734.41 r0 bottom value=2.20
R24 "RC0603FR-075R11L" 0603L 1547.44,1751.9 r90 bottom value=5.11
R25 "RC0402FR-0710KL" 0402L 1674.44,1779.46 r270 bottom value=10.0k
R26 "RC1206FR-07200KL" 1206L 2097.22,1819.15 r180 bottom value=200k
R27 "RC0402JR-070RL" 0402L 1422.59,852.72 r270 bottom value=0
R28 "RC0402JR-070RL" 0402L 1426.75,1069.27 r270 bottom value=0
R29 "RC0402JR-070RL" 0402L 2242.92,1025.93 r0 bottom value=0
R30 "RCS04022R20FKED" 0402L 1937.57,1303.5 r180 bottom value=2.20
R31 "RC0402JR-070RL" 0402S 2244.87,1270.47 r0 bottom value=0
R32 "RT0402BRD0710KL" 0402L 1401.14,797.38 r0 bottom value=10.0k
R33 "RT0402BRD0710KL" 0402L 1425.05,961.38 r90 bottom value=10.0k
R34 "RT0402BRD0710KL" 0402L 2244.55,947.38 r0 bottom value=10.0k
R35 "RT0402BRD0710KL" 0402L 2243.07,1191.45 r0 bottom value=10.0k
R36 "RCS04022R20FKED" 0402L 1733.65,793.71 r0 bottom value=2.20
R37 "RC0402JR-070RL" 0402L 2239.55,1685.7 r0 bottom value=0
R38 "RC0402JR-070RL" 0402L 2232.92,1443.4 r0 bottom value=0
R39 "RC0402JR-070RL" 0402L 1457.04,1293.12 r180 bottom value=0
R40 "RC0402JR-070RL" 0402L 1446.59,1468.16 r180 bottom value=0
R41 "RT0402BRD0710KL" 0402L 2264.41,1771.05 r270 bottom value=10.0k
R42 "RT0402BRD0710KL" 0402L 2235.67,1532.9 r0 bottom value=10.0k
R43 "RT0402BRD0710KL" 0402L 1421.82,1199.6 r90 bottom value=10.0k
R44 "RT0402BRD0710KL" 0402L 1426.75,1559.6 r270 bottom value=10.0k
T1 "PAT6561NL" FP-PAT6561NL_PTH_TRANSFORMER_40MM5_32MM5-MFG 1366.26,1248.35 r0 bottom locked
U1 "UCC5350SBDR" D0008B_HV 176,1230.98 r0 bottom
U2 "UCC27614DSG" DSG0008A-MFG 855.99,823.23 r0 bottom
U3 "UCC27614DSG" DSG0008A-MFG 861.81,1760.79 r180 bottom
U4 "UCC5350SBDR" D0008B_HV 1364.52,1751.9 r0 bottom
U5 "UCC27614DSG" DSG0008A-MFG 1849.49,1253 r180 bottom
U6 "UCC27614DSG" DSG0008A-MFG 1835.42,823.23 r0 bottom

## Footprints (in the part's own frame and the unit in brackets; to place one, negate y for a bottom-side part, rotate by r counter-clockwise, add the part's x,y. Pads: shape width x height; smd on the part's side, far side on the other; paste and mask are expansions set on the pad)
0402L [mm] "0402 from SM-752 data"
  rect 0.6x0.5 smd: 1(-0.5,0) 2(0.5,0)
  body extent -0.55,-0.3 0.55,0.3, height 0.6
0402S [mil] "Based on C0402S footprint from PADS legacy"
  rect 15x24 smd: 1(-20,0) 2(20,0)
  body extent -22,-12 22,12, height 24
0603L [mm] "0603 from SM-752 data"
  rect 0.8x0.85 smd: 1(-0.7,0) 2(0.7,0)
  silkscreen extent -0.07,-0.33 0.07,0.33, body extent -0.87,-0.47 0.87,0.47, height 1
1206L [mm] "1206 from SM-752 data"
  rect 1.1x1.75 smd: 1(-1.35,0) 2(1.35,0)
  silkscreen extent -0.4,-0.77 0.4,0.77, body extent -1.7,-0.9 1.7,0.9, height 1.35
D0008B_HV [mm] "SOIC, 8-Leads, Body 4.9x3.9mm, Pitch 1.27mm, HV / Isolation option"
  rrect17% 1.4x0.6 smd: 1(-2.75,1.905) 2(-2.75,0.635) 3(-2.75,-0.635) 4(-2.75,-1.905) 5(2.75,-1.905) 6(2.75,-0.635) 7(2.75,0.635) 8(2.75,1.905)
  silkscreen extent -3.3,-2.5 0.9,2.5, body extent -3,-2.45 3,2.45, height 1.63
DSG0008A-MFG [mm]
  rrect40% 0.5x0.25 smd paste+0 mask+0: 1(-0.95,0.75) 2(-0.95,0.25) 3(-0.95,-0.25) 4(-0.95,-0.75) 5(0.95,-0.75) 6(0.95,-0.25) 7(0.95,0.25) 8(0.95,0.75)
  rrect11% 0.9x1.6 smd paste-1000 mask+0: 9(0,0)
  silkscreen extent -1.87,-1.39 1,1.4, body extent -1,-1 1,1, height 0.8
FP-M50-3900642_HDR12-MFG [mm]
  rrect9% 1.12x1.12 hole 0.65 paste-1000 mask+0: 1(-3.175,3)
  round 1.12 hole 0.65 paste-1000 mask+0: 2(-3.175,4.27) 3(-1.905,3) 4(-1.905,4.27) 5(-0.635,3) 6(-0.635,4.27) 7(0.635,3) 8(0.635,4.27) 9(1.905,3) 10(1.905,4.27) 11(3.175,3) 12(3.175,4.27)
  silkscreen extent -4.48,-0.58 4.01,3.12, body extent -4.11,-4.9 4.11,4.93, height 0.25
FP-PAT6561NL_PTH_TRANSFORMER_40MM5_32MM5-MFG [mm]
  rrect100% 7.6x1.9 hole 1.3 slot 7 at 0 deg paste-1000 mask+0: 3(-12,8) 4(-12,3.7) 5(-12,-3.7) 6(-12,-8) 7(12,-8) 8(12,-3.7) 9(12,3.7) 10(12,8)
  silkscreen extent -20.85,-16.25 20.25,16.25, body extent -20.25,-20.25 20.25,20.25, height 30.5
Keystone_575-4 [mm] "Banana Jack"
  round 10 hole 5.45: 1(0,0)
  body extent -3.95,-3.95 3.92,3.93, height 2.36
PG-TDSON-8 [mm] "Infineon recommended land pattern"
  rect 1.2x0.65 smd: 1(-2.825,1.905) 2(-2.825,0.635) 3(-2.825,-0.635) 4(-2.825,-1.905)
  rect 0.5x0.7 smd: 5(3.175,-2) 6(3.175,-0.675) 7(3.175,0.675) 8(3.175,2)
  rect 4.5x4.7 smd paste-2.25: 9(0.675,0)
  silkscreen extent -3.74,-3 3.74,3, body extent -3.17,-2.89 3.17,2.9, height 1.1
SMA [mm] "Molded Diode, 2-Leads, Body 4.3x2.6mm, IPC Medium Density, based on OnSemi component dimensions and land pattern"
  rect 2x2 smd: 1(-2,0) 2(2,0)
  silkscreen extent -3.66,-1.57 2.79,1.57, body extent -2.6,-1.3 2.6,1.3, height 2.42

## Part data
C1 C15: library part CMP-0006939-4, "CAP, CERM, 47 pF, 50 V, +/- 5%, C0G/NP0, 0603", Cap_Case=0603, Manufacturer=Kemet, Supplier Part Number 1=399-1056-1-ND, TempCo=C0G/NP0, Tolerance_%=5%, Value1=Unknown, Value2=50V, ValueDisplayed=47pF
C2 C3 C16 C17: library part CMP-0006867-4, "CAP, CERM, 1 uF, 25 V, +/- 10%, X7R, 0603", Cap_Case=0603, Manufacturer=Kemet, Supplier Part Number 1=399-7376-1-ND, TempCo=X7R, Tolerance_%=10%, Value1=Unknown, Value2=25V, ValueDisplayed=1uF
C4 C5 C6 C7 C8 C18 C19 C20 C21 C22: library part CMP-0008992-2, "CAP, CERM, 1 uF, 50 V, +/- 10%, X7R, 1206", Cap_Case=1206, Manufacturer=MuRata, Supplier Part Number 1=GRM31MR71H105KA88L-ND, TempCo=X7R, Tolerance_%=10%, Value1=Unknown, Value2=50V, ValueDisplayed=1uF
C9 C12 C23 C26: library part CMP-0006467-2, "CAP, CERM, 47 pF, 50 V, +/- 1%, C0G/NP0, 0402", Cap_Case=0402, Manufacturer=MuRata, Supplier Part Number 1=490-6241-1-ND, TempCo=C0G/NP0, Tolerance_%=1%, Value1=Unknown, Value2=50V, ValueDisplayed=47pF
C10 C13 C24 C27: library part CMP-0006859-4, "CAP, CERM, 0.1 uF, 25 V, +/- 10%, X7R, 0603", Cap_Case=0603, Manufacturer=Kemet, Supplier Part Number 1=399-1281-1-ND, TempCo=X7R, Tolerance_%=10%, Value1=Unknown, Value2=25V, ValueDisplayed=0.1uF
C11 C14 C25 C28: library part CMP-0076705-3, "CAP, CERM, 1 µF, 25 V,+/- 10%, X7R, AEC-Q200 Grade 1, 0603", Cap_Case=1.6x0.8x0.8mm, Manufacturer=TDK, Supplier Part Number 1=445-6931-1-ND, TempCo=X7R, Tolerance_%=10%, Value2=25V, ValueDisplayed=1µF
D1 D3: library part CMP-0005517-4, "Diode, Zener, 36 V, 3 W, SMA", Manufacturer="Micro Commercial Components", Power_W=3W
D2 D4: library part CMP-0028585-2, "Diode, Schottky, 60 V, 1 A, SMA", Manufacturer="ON Semiconductor", Value1=1A, Value2=0.72V
J1: library part CMP-0093439-1, "Connector Header Through Hole, Right Angle 12 position 0.050\" (1.27mm)", Current_A=1A, Digikey Part Number=952-1396-ND, Manufacturer=Harwin, Mouser Part Number=855-M50-3900642, Operating Temperature Range="-40°C to +105°C"
J2 J3: library part CMP-0055165-2, "Standard Banana Jack, Uninsulated, 5.5mm", Manufacturer=Keystone, Supplier Part Number 1=36-575-4-ND
Q1 Q2 Q3 Q4 Q5 Q6 Q7 Q8 Q9 Q10 Q11 Q12 Q13 Q14 Q15 Q16 Q17 Q18: library part CMP-0000292-1, "MOSFET, N-CH, 30 V, 100 A, PG-TDSON-8", Alternate Manufacturer=None, Manufacturer="Infineon Technologies", PartNumber="BSC014N03MS G", Supplier Part Number 1="BSC014N03MS G-ND", Value1=0.001, Value2="63 nC"
R1 R23: library part CMP-0022711-2, "RES, 2.20, 1%, 0.1 W, 0603", Manufacturer=Panasonic, Power_W=100mW, Supplier Part Number 1=P2.2AJCT-ND, TempCo="200 ppm/C", Tolerance_%=1%, Value2=0.1W, Value_Code=2R20, ValueDisplayed=2.20
R2 R24: library part CMP-0023206-5, "RES, 5.11, 1%, 0.1 W, 0603", Manufacturer=Yageo, Power_W=100mW, Supplier Part Number 1=311-5.11HRCT-ND, TempCo="200 ppm/C", Tolerance_%=1%, Value2=0.1W, Value_Code=5R11, ValueDisplayed=5.11
R3 R25: library part CMP-0078669-1, "RES, 10.0 k, 1%, 0.063 W, 0402", Manufacturer="Yageo America", Power_W=63mW, Supplier Part Number 1=311-10.0KLRCT-ND, TempCo="100 ppm/C", Tolerance_%=1%, Value2=0.063W, Value_Code=10k0, ValueDisplayed=10.0k
R4 R26: library part CMP-0018060-2, "RES, 200 k, 1%, 0.25 W, 1206", Manufacturer="Yageo America", Power_W=250mW, Supplier Part Number 1=311-200KFRCT-ND, TempCo="100 ppm/C", Tolerance_%=1%, Value2=0.25W, Value_Code=200k
R5 R16 R30 R36: library part CMP-0026747-1, "RES, 2.20, 1%, 0.2 W, 0402", Manufacturer=Vishay-Dale, Power_W=200mW, Supplier Part Number 1=RCS04022R20FKED-ND, TempCo="100 ppm/C", Tolerance_%=1%, Value2=0.2W, Value_Code=2R20, ValueDisplayed=2.20
R6 R7 R8 R9 R14 R15 R17 R18 R27 R28 R29 R31 R37 R38 R39 R40: library part CMP-0027004-2, "RES, 0, 5%, 0.063 W, 0402", Manufacturer="Yageo America", Power_W=63mW, Supplier Part Number 1=311-0.0JRCT-ND, TempCo="200 ppm/C", Tolerance_%=5%, Value2=0.063W, Value_Code=0000, ValueDisplayed=0
R10 R11 R12 R13 R19 R20 R21 R22 R32 R33 R34 R35 R41 R42 R43 R44: library part CMP-0065360-1, "RES, 10.0 k, .1%, .0625 W, 0402", Manufacturer="Yageo America", Power_W=62.5mW, Supplier Part Number 1=YAG1346CT-ND, TempCo="25 ppm/C", Tolerance_%=0.1%, Value1=.1%, Value2=.0625W, Value_Code=10k0, ValueDisplayed=10.0k
T1: library part CMP-0093678-1, "XFMR, PSFB, 3KW, EW39, TH", Frequency_Fixed=100kHz, Manufacturer=Pulse, Operating Temperature Range="-40°C to +125°C", Voltage_Isolation_Vrms=3kV
U1 U4: library part CMP-0077706-1, "3-kVRMS Single-Channel Isolated Gate Drivers, D0008B (SOIC-8)", Alternate Manufacturer="Texas Instruments", Alternate PartNumber=UCC5350SBD
U2 U3 U5 U6: library part CMP-0090339-1, "Single Channel 30V 10A High Speed Low Side Gate Driver", Manufacturer="Texas Instruments", Max Supply Voltage=26V, Min Supply Voltage=4.5V, Nominal Supply Current=175uA, Operating Temperature Range="-40°C to +150°C", Output Voltage=0-26V

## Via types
v1: diameter 24, hole 8, Top Layer to Bottom Layer, tented both sides, 1021 vias
v2: diameter 19.68, hole 7.87, Top Layer to Bottom Layer, 8 vias
v3: diameter 19.68, hole 7.87, Top Layer to Bottom Layer, tented both sides, 1 vias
